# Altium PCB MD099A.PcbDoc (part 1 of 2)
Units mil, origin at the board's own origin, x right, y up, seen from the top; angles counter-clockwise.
Board outline 4255 x 2850 mil, 4 copper layers (Top Layer, Ground, Power, Bottom Layer), stack 61.6 mil thick; 151 components, 81 nets, 392 pads, 633 vias.
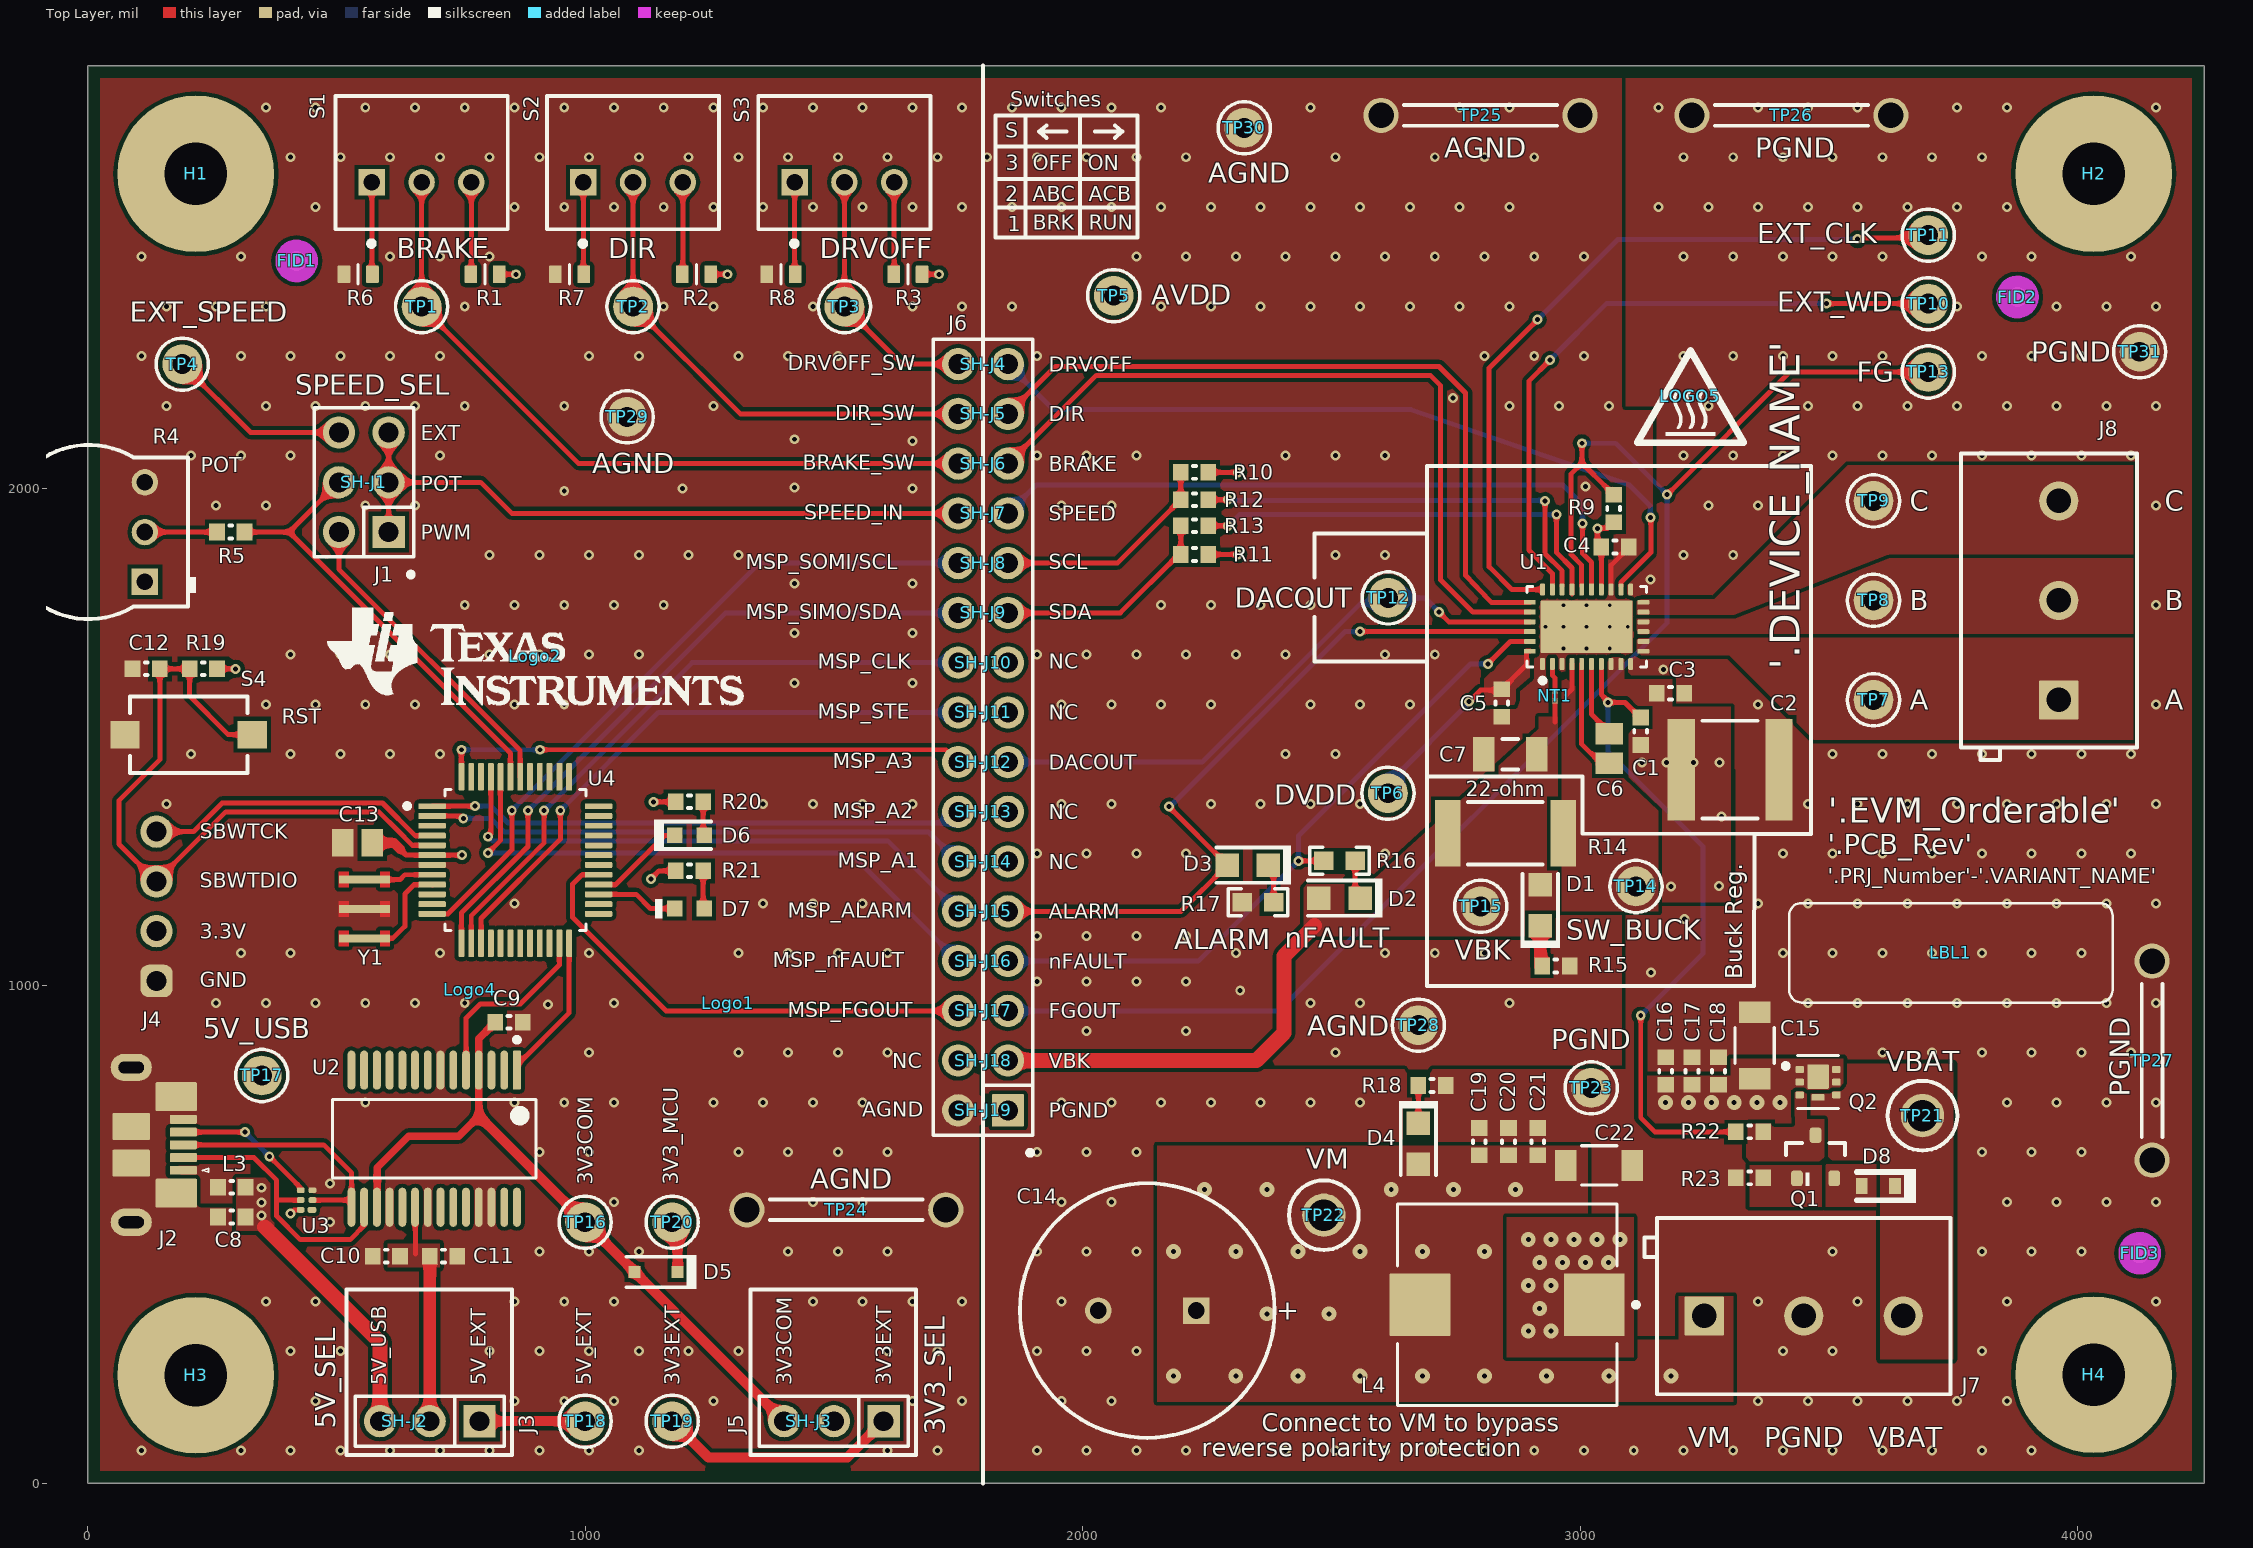
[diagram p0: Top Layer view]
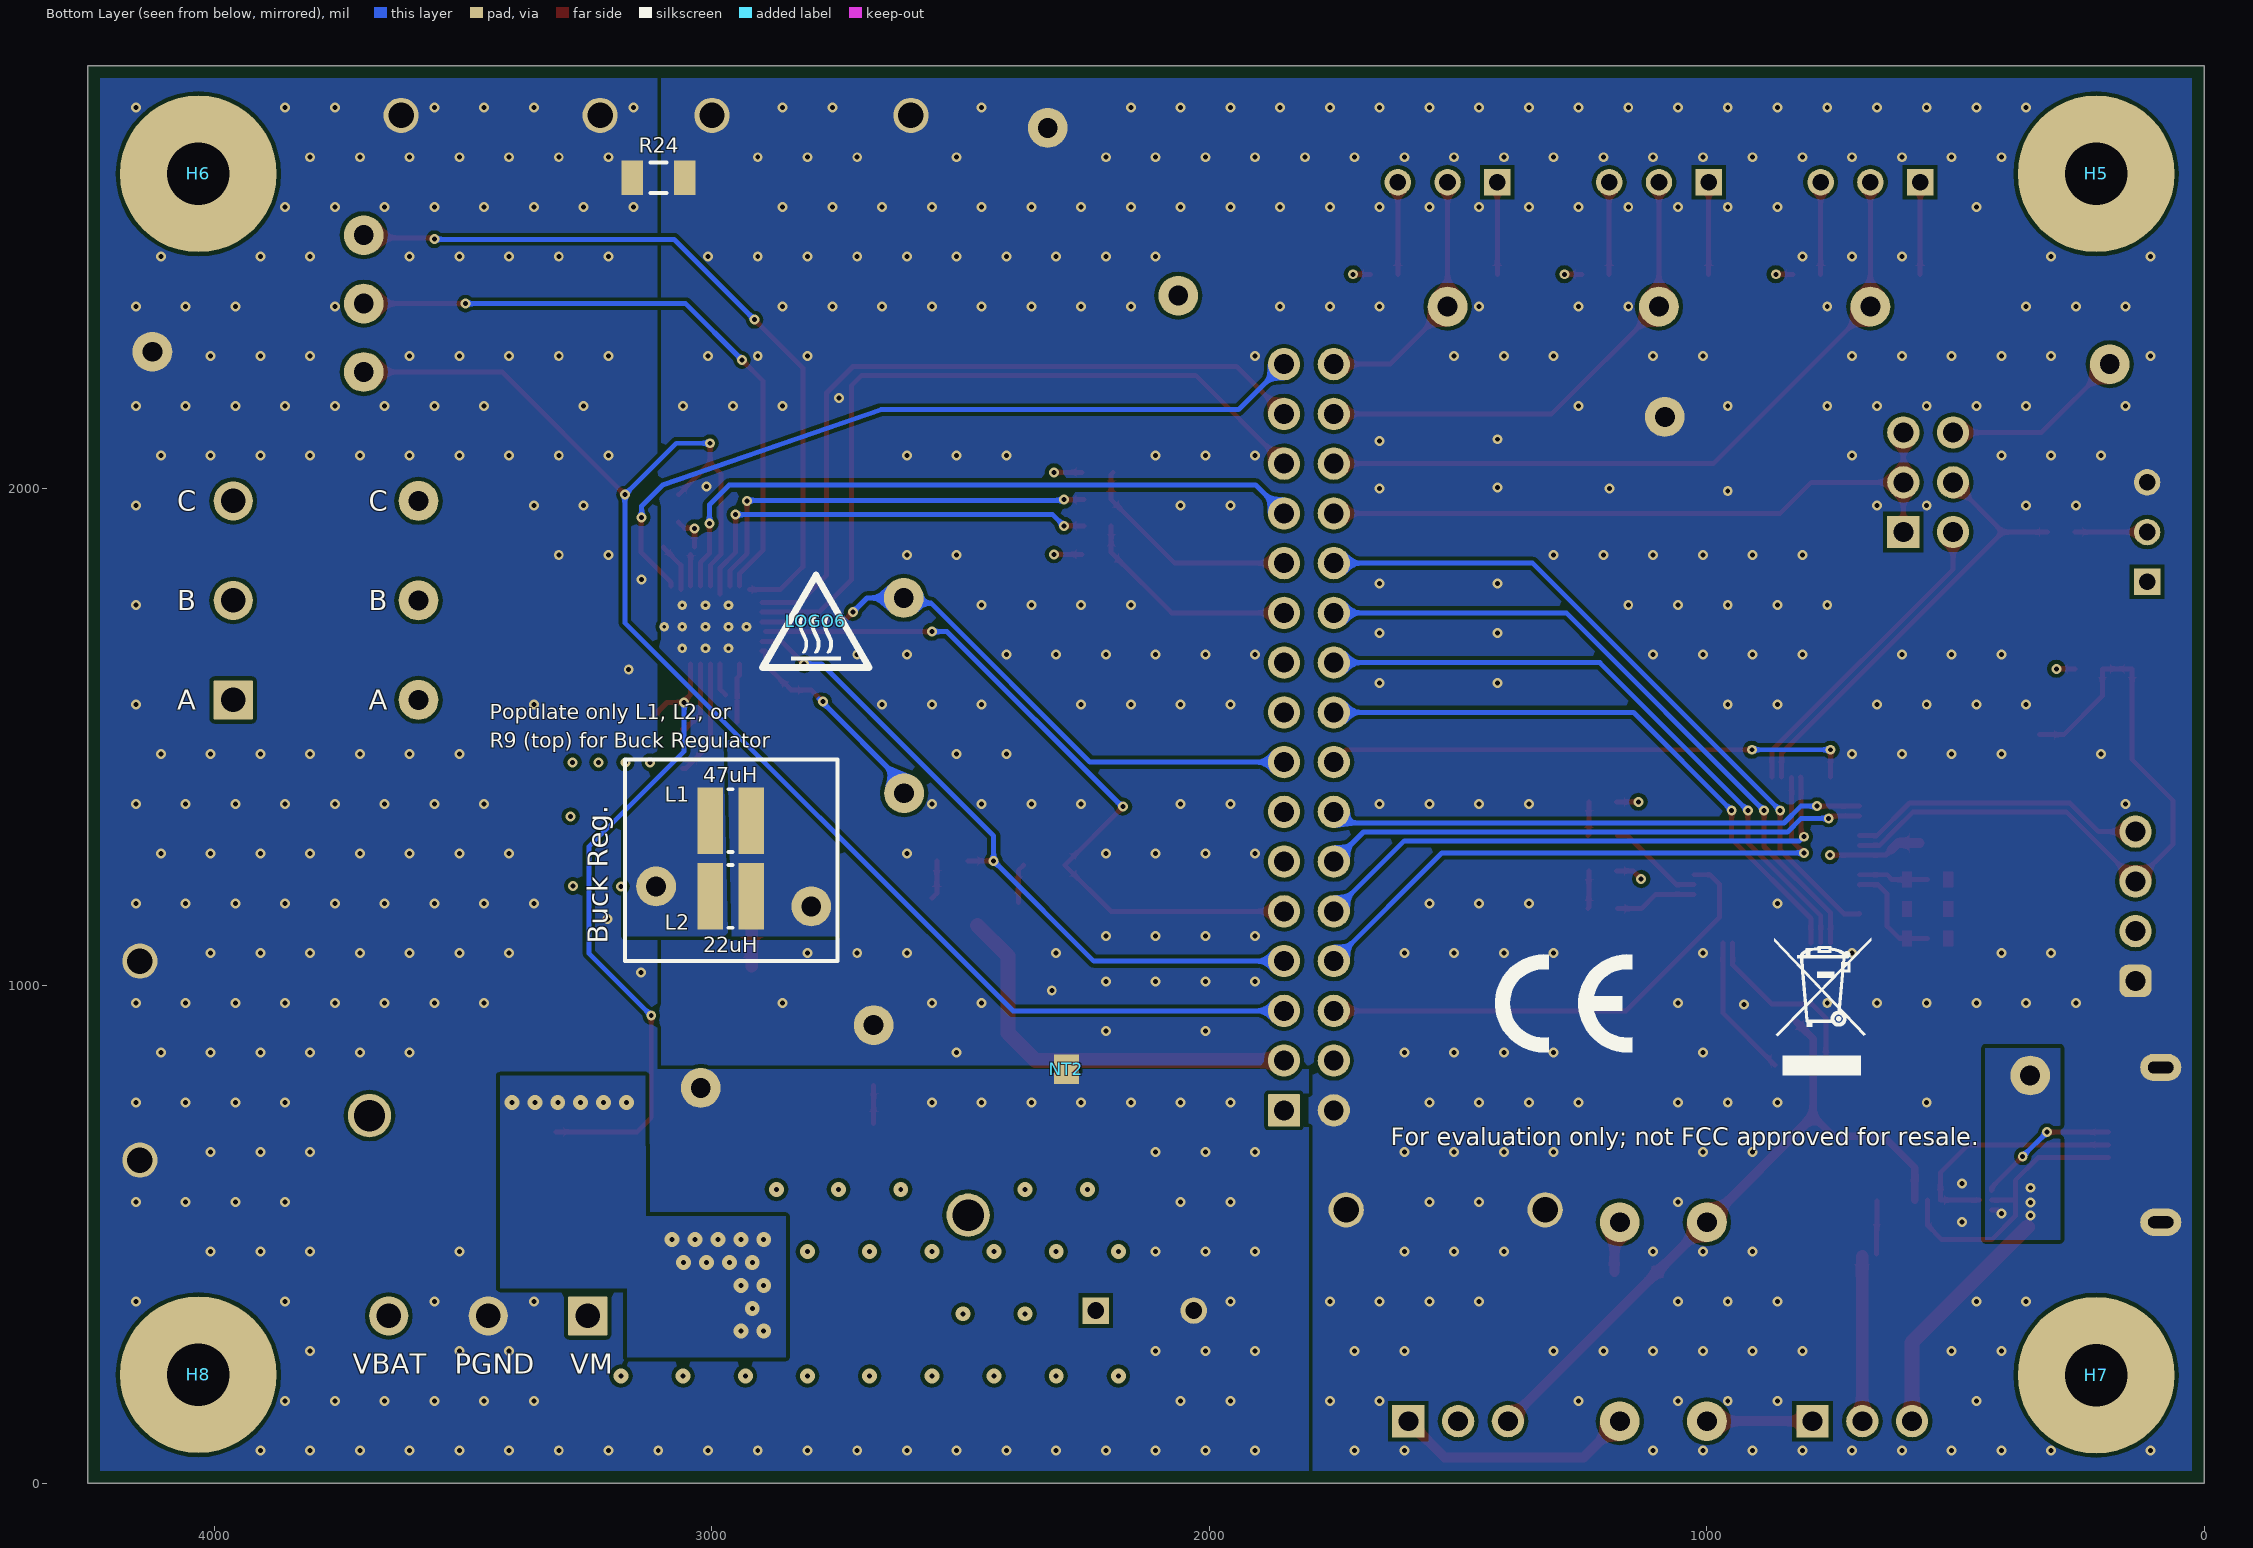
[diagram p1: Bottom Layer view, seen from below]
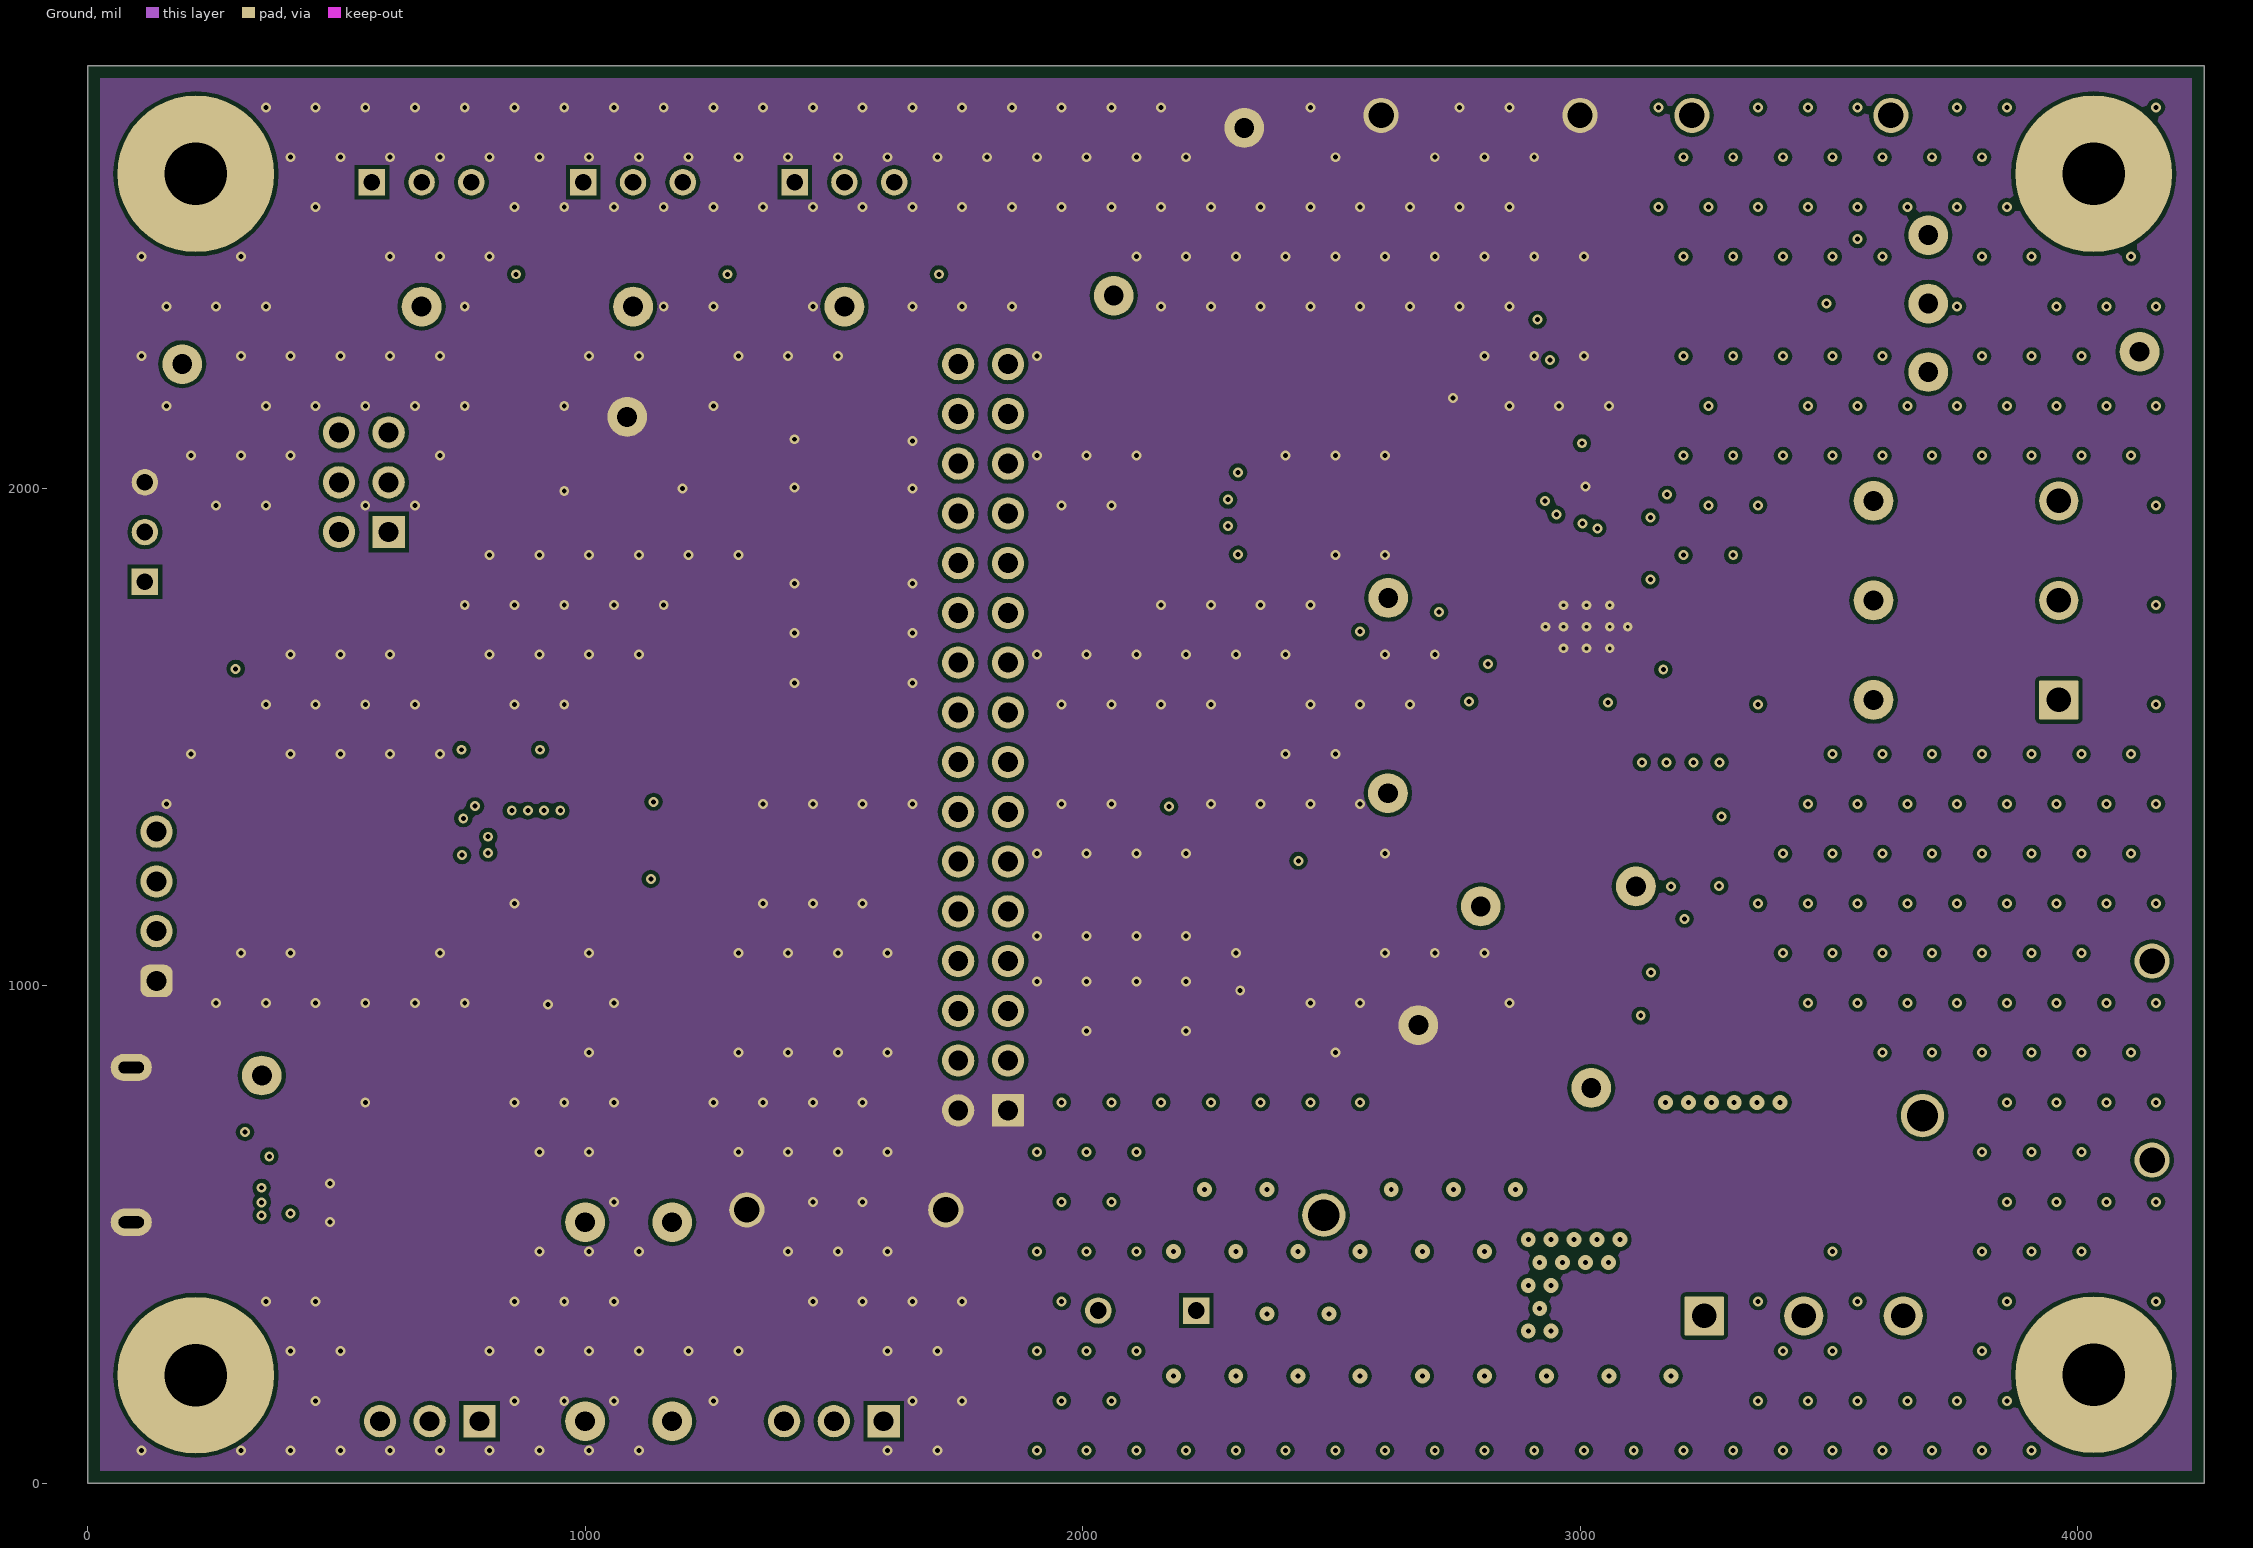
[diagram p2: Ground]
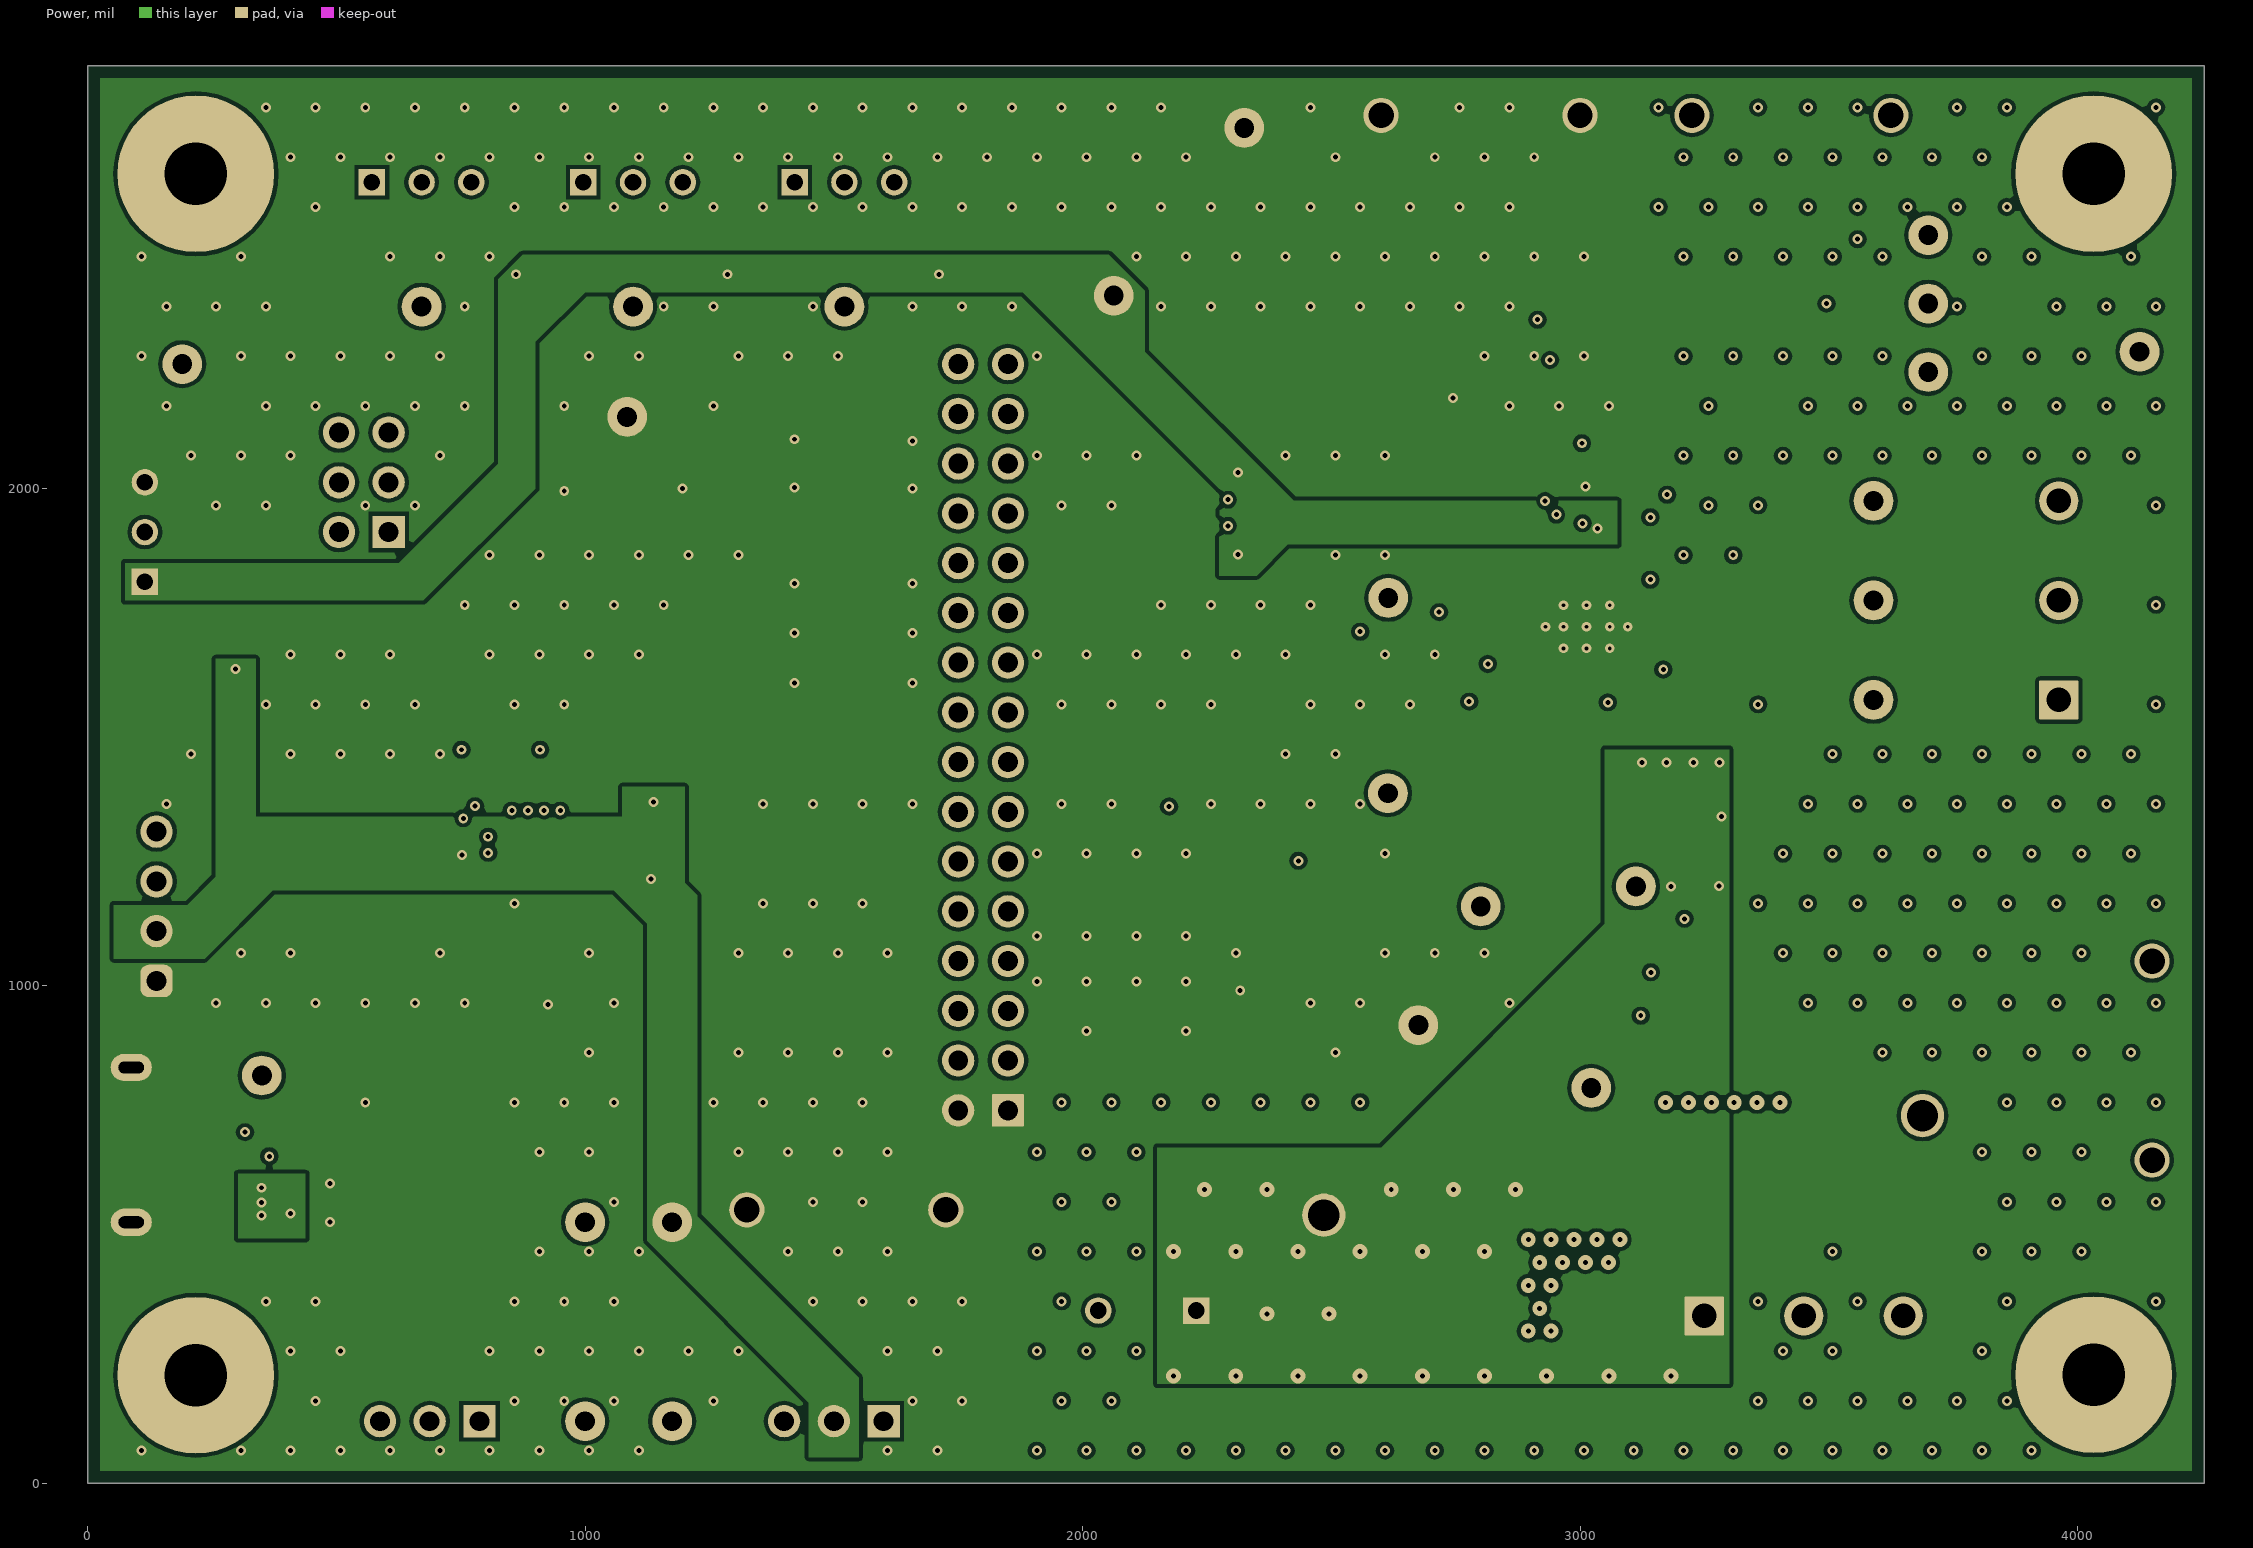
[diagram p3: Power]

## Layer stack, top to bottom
Top Solder: solder mask 0.4, Solder Resist, Dk 3.5
Top Layer: signal copper 1.4
Dielectric 1: prepreg 8, FR-4, Dk 4.2
Ground: signal copper 1.4
Dielectric 2: core 40, FR-4, Dk 4.2
Power: signal copper 1.4
Dielectric 3: prepreg 8, FR-4, Dk 4.2
Bottom Layer: signal copper 1.4
Bottom Solder: solder mask 0.4, Solder Resist, Dk 3.5

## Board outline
0,0 0,2850 4255,2850 4255,0

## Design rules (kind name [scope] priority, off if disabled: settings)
AcuteAngle [All] p1: minimum=4.50000000000000E+0001 checktracksonly=FALSE
AssemblyTestPointUsage [All] p1: valid=2
BoardOutlineClearance BoardOutlineClearance_MountingHoles [OnCopper and InComponentClass('Mounting Holes')] p1: gap=39.37 ignorepadtopadclearanceinfootprint=FALSE
BoardOutlineClearance BoardOutlineClearance_Poly [OnCopper and IsPoly] p2: gap=25 ignorepadtopadclearanceinfootprint=FALSE
BoardOutlineClearance [OnCopper and Not InComponentClass('Logo') and not InComponentClass('FiducialMark') and not InRegion(1000,500,4000,800) and not InPoly] p3: gap=30 ignorepadtopadclearanceinfootprint=FALSE
Clearance "Stitching AGND" [IsStitchingVia and InNet('AGND') vs (IsVia and (Not IsStitchingVia)) Or IsPad] p1: gap=70 ignorepadtopadclearanceinfootprint=TRUE
Clearance Clearance_Keepouts [((IsTrack Or IsArc) And Not InPoly) And IsFree and IsKeepOut vs ((IsTrack Or IsArc) And Not InPoly) And IsFree and IsKeepOut] p2: gap=0 ignorepadtopadclearanceinfootprint=FALSE
Clearance Clearance_Poly [InPolygon] p3: gap=7.87 ignorepadtopadclearanceinfootprint=TRUE
Clearance Clearance_FiducialMark [IsKeepOut and InComponentClass('FiducialMark') vs IsPad and InComponentClass('FiducialMark')] p4: gap=0 ignorepadtopadclearanceinfootprint=FALSE
Clearance [All] p5: gap=7.87 ignorepadtopadclearanceinfootprint=TRUE
ComponentClearance ComponentClearance_MountingHoles_FiducialMarks [InComponentClass('Mounting Holes') vs InComponentClass('FiducialMark')] p1: gap=50 collisioncheckmode=3 verticalgap=10 showdistances=FALSE
ComponentClearance ComponentClearance_Shunt [InComponentClass('Header') vs InComponentClass('Shunt')] p2: gap=0 collisioncheckmode=3 verticalgap=0 showdistances=FALSE
ComponentClearance ComponentClearance_Logo [InComponentClass('Logo')] p3: gap=50 collisioncheckmode=3 verticalgap=10 showdistances=FALSE
ComponentClearance ComponentClearance_ScrewToNut [(HasFootprint('NY PMS 440 0025 PH')) vs (HasFootprint('Keystone_1902C'))] p4: gap=5 collisioncheckmode=3 verticalgap=10 showdistances=FALSE
ComponentClearance ComponentClearance_MountingHoles [InComponentClass('Mounting Holes')] p5: gap=150 collisioncheckmode=3 verticalgap=100000 showdistances=FALSE
ComponentClearance ComponentClearance_SmallPassives [HasFootprint('0201*') or HasFootprint('0402*') or HasFootprint('0508') or HasFootprint('0603*') or HasFootprint('0612') or HasFootprint('0805*') or HasFootprint('0815*') or HasFootprint('0830*') or HasFootprint('1206*') or HasFootprint('1210*') or HasFootprint('1808*') or HasFootprint('1812*') or HasFootprint('1825*') or HasFootprint('2010*') or HasFootprint('2220*') or HasFootprint('2225*') or HasFootprint('2512*') or HasFootprint('2728*') or HasFootprint('3518*') vs HasFootprint('0201*') or HasFootprint('0402*') or HasFootprint('0508') or HasFootprint('0603*') or HasFootprint('0612') or HasFootprint('0805*') or HasFootprint('0815*') or HasFootprint('0830*') or HasFootprint('1206*') or HasFootprint('1210*') or HasFootprint('1808*') or HasFootprint('1812*') or HasFootprint('1825*') or HasFootprint('2010*') or HasFootprint('2220*') or HasFootprint('2225*') or HasFootprint('2512*') or HasFootprint('2728*') or HasFootprint('3518*')] p6: gap=14.96 collisioncheckmode=3 verticalgap=10 showdistances=FALSE
ComponentClearance ComponentClearance_THtoSMT [IsThruComponent vs IsSMTComponent] p7: gap=0 collisioncheckmode=3 verticalgap=0 showdistances=FALSE
ComponentClearance ComponentClearance_THtoTH [IsThruComponent vs IsThruComponent] p8: gap=0 collisioncheckmode=3 verticalgap=0 showdistances=FALSE
ComponentClearance [All] p9: gap=0 collisioncheckmode=3 verticalgap=0 showdistances=FALSE
DiffPairsRouting [All] p1: maxlimit=100 minlimit=10 mostfreqgap=10 toplayer_minwidth=15 toplayer_maxwidth=15 toplayer_prefwidth=15 midlayer1_minwidth=15 midlayer1_maxwidth=15 midlayer1_prefwidth=15 midlayer2_minwidth=15 midlayer2_maxwidth=15 midlayer2_prefwidth=15 bottomlayer_minwidth=15 bottomlayer_maxwidth=15 bottomlayer_prefwidth=15 maxuncoupledlength=1000
FabricationTestPointUsage TestPointUsage [All] p1: valid=2 allowmultiple=FALSE
FabricationTestpoint Testpoint [All] p1: side=3 testpointundercomponent=TRUE minsize=40 maxsize=100 preferedsize=60 minholesize=0 maxholesize=40 preferedholesize=32 testpointgrid=1 allowsidetop=TRUE allowsidebottom=TRUE usegrid=TRUE gridtolerance=0.01
FanoutControl Fanout_LCC [IsLCC] p1: bgadir=Out bgaviamode=Centered fanoutstyle=Auto fanoutdirection=Alternating viagrid=1 // Fanout_LCC (Default Rule)
FanoutControl Fanout_BGA [IsBGA] p2: bgadir=Out bgaviamode=Centered fanoutstyle=Auto fanoutdirection=Alternating viagrid=1 // Fanout_BGA (Default Rule)
FanoutControl Fanout_Default [All] p4: bgadir=Out bgaviamode=Centered fanoutstyle=Auto fanoutdirection=Alternating viagrid=1 // Fanout_Default (Default Rule)
FanoutControl Fanout_Small [(CompPinCount < 5)] p5: bgadir=Out bgaviamode=Centered fanoutstyle=Auto fanoutdirection=OutThenIn viagrid=1 // Fanout_Small (Default Rule)
HoleSize [All] p1: absolutevalues=TRUE maxlimit=200 minlimit=1 maxpercent=80.000 minpercent=20.000
MinimumAnnularRing MinimumAnnularRing_ThermalPadVias [IsVia and InAnyComponent] p1: minimumring=1
MinimumAnnularRing [All] p2: minimumring=1
MinimumSolderMaskSliver MinimumSolderMaskSliver_Logo [InComponentClass('Logo') vs InComponentClass('Logo')] p1: minsoldermaskwidth=0.7
MinimumSolderMaskSliver [All] p2: minsoldermaskwidth=1
PlaneConnect [All] p1: planeconnectstyle=Relief reliefexpansion=10 reliefentries=4 reliefconductorwidth=10 reliefairgap=10
PolygonConnect [All] p1: connectstyle=Direct reliefconductorwidth=10 reliefentries=4 polygonreliefangle="90 Angle" airgapwidth=10
RoutingVias ThermalPadVias [IsVia and InAnyComponent] p1: holewidth=7.87 width=19.68 viastyle="Through Hole" minholewidth=7.87 minwidth=19.68 maxholewidth=12.99 maxwidth=23.62
RoutingVias [All] p2: holewidth=10 width=25 viastyle="Through Hole" minholewidth=7 minwidth=20 maxholewidth=15 maxwidth=30
SilkToBoardRegionClearance [Not ((IsComment or IsDesignator) And (Hide <> 'False')) and not InRegion(1000,500,4000,800)] p1:
SilkToSilkClearance SilkToSilkClearance_Pb-FreeLogo [(HasFootprint('Pb-Free_Overlay_Medium') OR HasFootprint('Pb-Free_Overlay_Small')) vs (HasFootprint('Pb-Free_Overlay_Medium') OR HasFootprint('Pb-Free_Overlay_Small'))] p1: silktosilkclearance=1
SilkToSilkClearance [All] p2: silktosilkclearance=1
SilkToSolderMaskClearance [IsPad] p1: minsilkscreentomaskgap=1 clearancetoexposedcopper=TRUE
SolderMaskExpansion [All] p1: expansion=1.97 istentingtop=FALSE
UnRoutedNet [All] p1: checkbadconnections=TRUE
Width [All] p1: maxlimit=100 minlimit=6 preferedwidth=10 checkconnectedcopper=TRUE
14 further rules are at their usual default settings.

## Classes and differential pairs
component class Label: LBL1 LBL044_026
component class "Mounting Holes": H1 H2 H3 H4 H009_017 H009_041 H047_017
component class MD099_INTERFACE: C8 C9 C10 C11 C12 C012_028 C13 C014_019 C015_024 C038_030 C039_029 D5 D6 D7 D019_028 D032_027 D036_026 J2 J3 J4 J5 J6 J007_022 J008_026 J021_016 J024_030 L3 L036_028 R016_039 R19 R20 R21 R029_035 R035_028 S4 S017_041 SH-J2 SH-J3 SH-J4 SH-J5 SH-J6 SH-J7 SH-J8 SH-J9 SH-J10 SH-J11 SH-J12 SH-J13 SH-J013_016 SH-J14 SH-J15 SH-J16 SH-J17 SH-J18 SH-J19 SH-J021_016 SH-J024_022 SH-J024_023 SH-J024_024 SH-J024_031 SH-J024_032 SH-J024_034 SH-J024_035 SH-J024_036 TP013_039 TP16 TP17 TP18 TP19 TP20 TP022_020 TP038_027 TP042_031 U2 U3 U4 U011_021 U013_022 U037_032 Y1 Y012_026
component class MD099_CONTROL: J1 J008_026 R1 R2 R3 R4 R5 R6 R7 R8 R009_034 R012_039 R014_039 R029_035 R035_028 R037_034 S1 S2 S3 S008_030 S017_041 SH-J1 SH-J012_035 TP1 TP2 TP3 TP4 TP008_037 TP022_020 TP043_039
component class Shunt: SH-J1 SH-J2 SH-J3 SH-J4 SH-J5 SH-J6 SH-J7 SH-J8 SH-J9 SH-J10 SH-J11 SH-J12 SH-J012_035 SH-J13 SH-J013_016 SH-J14 SH-J15 SH-J16 SH-J17 SH-J18 SH-J19 SH-J021_016 SH-J024_022 SH-J024_023 SH-J024_024 SH-J024_031 SH-J024_032 SH-J024_034 SH-J024_035 SH-J024_036
component class MD099_POWER_AND_CONNECTORS: AGND AGND1 C012_028 C14 C014_019 C15 C16 C17 C18 C19 C20 C21 C22 C028_018 C036_022 C038_030 C039_029 D8 D042_021 J7 J8 J10 J11 J041_018 J046_033 L4 L036_027 NT2 NT029_023 PGND PGND2 PGND3 Q1 Q2 Q041_021 R22 R23 R24 R032_027 R036_025 R45 TP013_039 TP016_020 TP017_036 TP018_020 TP21 TP22 TP022_020 TP23 TP24 TP25 TP26 TP27 TP28 TP29 TP30 TP31 TP033_024 TP038_027 TP043_037 TP043_040 TP_AGND1 TP_AGND2 TP_PGND vm VM1
component class MD099_DRIVER: 1 A1 B1 C1 C2 C3 C4 C5 C6 C7 C012_028 C014_019 C015_024 C028_018 C034_022 C036_022 D1 D2 D3 D4 D018_019 D019_026 D019_028 ILIM1 L1 L2 L036_027 L036_028 NT1 NT036_031 R9 R10 R11 R12 R13 R14 R15 R16 R17 R18 R029_034 R029_035 TP5 TP6 TP7 TP8 TP9 TP10 TP11 TP12 TP13 TP013_039 TP14 TP15 TP017_036 TP018_020 TP022_020 TP034_042 TP038_027 TP042_031 TP043_039 U1 U011_021
component class Header: J1 J3 J4 J5 J6 J007_022 J008_026 J10 J021_016 J024_030
component class Logo: Logo2 Logo5
component class MD099_HARDWARE: FID1 FID2 FID3 FID011_039 FID045_039 FID048_019 H1 H2 H3 H4 H5 H6 H7 H8 H009_017 H009_041 H047_017 H047_041 LBL1 LBL044_026 Logo1 Logo2 Logo3 LOGO4 Logo5 LOGO6 Logo015_031 LOGO034_032 ZZ1 ZZ2 ZZ3 ZZ4 ZZ007_047 ZZ007_049
component class FiducialMark: FID1 FID2 FID3 FID011_039 FID045_039 FID048_019
component class AssemblyNote: ZZ1 ZZ2 ZZ3 ZZ4 ZZ007_047 ZZ007_049

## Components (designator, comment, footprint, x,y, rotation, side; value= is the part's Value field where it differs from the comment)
C1 "EMK107B7105KAHT" 0603L 3121.91,1511.99 r270 top value=1uF
C2 "22201C106MAT2A" 2220_280L 3301.65,1434.78 r0 top value=10uF
C3 "GRM188R72A104KA35D" 0603L 3182.03,1588.3 r0 top value=0.1uF
C4 "C0603C105K9RACAUTO" 0603L 3070.37,1882.5 r180 top value=1uF
C5 "GCM188R70J225KE22D" 0603L 2842.85,1568.83 r90 top value=2.2uF
C6 "CGA4J2X7R2A473K125AA" 0805L 3059.14,1477.04 r270 top value=0.047uF
C7 "GRM31CR71A226KE15L" 1206_180L 2859.96,1466 r180 top value=22uF
C8 "0603ZC104KAT2A" 0603L 289.64,535.59 r180 top value=0.1uF
C9 "0603ZC104KAT2A" 0603L 847.14,927.09 r0 top value=0.1uF
C10 "GRM188Z71A475ME15D" 0603L 600.29,456.84 r0 top value=4.7uF
C11 "0603ZC104KAT2A" 0603L 715.29,456.96 r0 top value=0.1uF
C12 "885012206034" 0603L 117.5,1637.5 r180 top value=1000pF
C13 "885012207103" 0805L 542.5,1287.5 r180 top value=1uF
C14 "ELXZ630ELL331MK20S" Chemi-Con_1250x2000 2130,347.5 r180 top value=330uF
C15 "CL31B105KCHNNNE" 1206_180 3350.96,880.34 r90 top value=1uF
C16 "CGA3E3X7S2A104K080AB" 0603L 3172.01,828.83 r90 top value=0.1uF
C17 "CGA3E2X7R2A103K080AA" 0603L 3225.22,828.83 r90 top value=0.01uF
C18 "CGA3E2X7R2A102K080AA" 0603L 3278.42,828.83 r90 top value=1000pF
C19 "CGA3E2X7R2A102K080AA" 0603L 2797.51,686.94 r90 top value=1000pF
C20 "CGA3E2X7R2A103K080AA" 0603L 2856.26,686.94 r90 top value=0.01uF
C21 "CGA3E3X7S2A104K080AB" 0603L 2915.01,686.94 r90 top value=0.1uF
C22 "CL31B105KCHNNNE" 1206_180 3038.46,639.14 r0 top value=1uF
D1 "LTST-C170KGKT" LTST-C170KGKT_Green 2920,1162.5 r270 top value=Green
D2 "LTST-C170KRKT" LED_LTST-C170_Red 2516.5,1176.5 r0 top value=Red
D3 "LTST-C170KRKT" LED_LTST-C170_Red 2332.16,1243 r0 top value=Red
D4 "LTST-C170KGKT" LTST-C170KGKT_Green 2675,682.5 r90 top value=Green
D5 "BAT165E6327HTSA1" SOD-323 1142.5,425 r180 top value=40V
D6 "LTST-C190KRKT" LED_LTST-C190_Red 1209.64,1302.7 r180 top value=Red
D7 "LTST-C190KGKT" LED_LTST-C190_G 1209.64,1155.59 r180 top value=Green
D8 "CDSU101A" SOD-523F 3599.64,597.8 r180 top value=90V
FID1 "Fiducial" Fiducial10-20 420,2457.5 r0 top locked
FID2 "Fiducial" Fiducial10-20 3879.4,2385 r0 top
FID3 "Fiducial" Fiducial10-20 4125,462.5 r0 top
H1 "NY PMS 440 0025 PH" "NY PMS 440 0025 PH" 217.5,2632.5 r0 top
H2 "NY PMS 440 0025 PH" "NY PMS 440 0025 PH" 4032.5,2632.5 r0 top
H3 "NY PMS 440 0025 PH" "NY PMS 440 0025 PH" 217.5,217.5 r0 top
H4 "NY PMS 440 0025 PH" "NY PMS 440 0025 PH" 4032.5,218.36 r0 top
H5 "Nut" Keystone_1902C 217.5,2632.5 r180 bottom
H6 "Nut" Keystone_1902C 4032.5,2632.5 r180 bottom
H7 "Nut" Keystone_1902C 217.5,217.5 r180 bottom
H8 "Nut" Keystone_1902C 4032.5,218.36 r180 bottom
J1 "Header_3x2" TSW-103-07-G-D 555.01,2012.5 r90 top
J2 "1051640001" Molex_1051640001 30.41,680.59 r270 top
J3 "Header_3x1" PBC03SAAN 687.5,125 r180 top
J4 "TSW-104-07-G-S" TSW-104-07-G-S 138.36,1160.18 r90 top
J5 "Header_3x1" PBC03SAAN 1500,125 r180 top
J6 "TSW-116-07-G-D" TSW-116-07-G-D 1800,1500 r90 top
J7 "POWER_IN" On-Shore_ED120_3DS 3449.83,336.64 r0 top
J8 "MOTOR_OUT" On-Shore_ED120_3DS 3962.5,1775 r90 top
L1 "78438335470" WE-MAIA_3015 2962.5,1332.5 r180 bottom value=47uH
L2 "78438335220" WE-MAIA_3015 2962.5,1180 r180 bottom value=22uH
L3 "BLM18SG121TZ1D" 0603L 289.64,595.24 r180 top
L4 "HCM1A1104V2-1R0-R" FP-HCM1A1104V2-1R0-R_SMD2-MFG 2853.46,359.14 r180 top value=1uH
LBL1 "THT-14-423-10" Label_650x200 3745.5,1066.57 r180 top
Logo1 "CE Mark" CE_Mark_5mm 1287.85,965 r180 top
Logo2 "Texas Instruments" TI_Stacked_Overlay_Small 900,1662.5 r0 top
Logo3 "FCC disclaimer" FCC_disclaimer 8817.5,5262.5 r90 top
Logo4 "WEEE logo" WEEE_Minimum 769.14,992.5 r180 top
LOGO5 "CAUTION HOT SURFACE" IEC_HotSurface_Small 3222.08,2185 r0 top
LOGO6 "CAUTION HOT SURFACE" IEC_HotSurface_Small 2791,1733.5 r180 bottom
NT1 "Net-Tie" Net-Tie_10mil 2949.39,1583.2 r270 top net-tie
NT2 "Net-Tie" Net-Tie_50milWide_30milLong 2287.5,832.5 r270 bottom net-tie
Q1 "FMMT620TA" SOT-23L 3473.46,656.64 r90 top value="80 V"
Q2 "BUK9D23-40EX" FP-BUK9D23-40EX_SOT1220-MFG 3478.46,806.64 r0 top
R1 "ERA-3ARB103V" FP-ERA-3ARB103V_0603-MFG 798.83,2430.7 r0 top value=10k
R2 "ERA-3ARB103V" FP-ERA-3ARB103V_0603-MFG 1223.83,2430.7 r0 top value=10k
R3 "ERA-3ARB103V" FP-ERA-3ARB103V_0603-MFG 1648.83,2430.7 r0 top value=10k
R4 "3352T-1-253LF" Bourns_3352T 115,1912.5 r90 top value="25 kohm"
R5 "ERJ-3GEY0R00V" 0603L 287.5,1912.5 r180 top value=0
R6 "ERA-3ARB103V" FP-ERA-3ARB103V_0603-MFG 543.77,2430.7 r0 top value=10k
R7 "ERA-3ARB103V" FP-ERA-3ARB103V_0603-MFG 968.71,2430.7 r0 top value=10k
R8 "ERA-3ARB103V" FP-ERA-3ARB103V_0603-MFG 1393.71,2430.7 r0 top value=10k
R9 "CRCW06035K10JNEA" 0603L 3067.5,1960 r270 top value=5.1k
R10 "CRCW06035K10JNEA" 0603L 2225,2032.5 r180 top value=5.1k
R11 "CRCW06035K10JNEA" 0603L 2225,1867.5 r180 top value=5.1k
R12 "ERJ-3GEY0R00V" 0603L 2225,1977.5 r0 top value=0
R13 "ERJ-3GEY0R00V" 0603L 2225,1925 r0 top value=0
R14 "CRCW251222R0JNEGHP" 2512 2850,1306.76 r180 top value=22
R15 "RC0603FR-071KL" 0603L 2951.5,1040 r180 top value=1.00k
R16 "RC0603FR-071KL" 0603 2516.5,1251.5 r0 top value=1.00k
R17 "RC0603JR-07470RL" 0603 2352.5,1168 r0 top value=470
R18 "RT0603BRD074K7L" 0603L 2702.56,800 r180 top value=4.70k
R19 "RC0603JR-0747KL" 0603L 232.5,1637.5 r0 top value=47k
R20 "RC0603JR-07470RL" 0603L 1209.64,1370.2 r180 top value=470
R21 "RC0603JR-07470RL" 0603L 1209.64,1231.43 r180 top value=470
R22 "CRCW060310K0JNEA" 0603L 3340.96,706.64 r0 top value=10k
R23 "CRCW060310K0JNEA" 0603L 3340.96,614.14 r180 top value=10k
R24 "RCA12060000ZSEA" 1206L 3107.5,2625 r0 bottom value=0
S1 "SW_SPDT_COM2_1_3" SW_B12AP 671.27,2655.07 r90 top
S2 "SW_SPDT_COM2_1_3" SW_B12AP 1096.27,2655.07 r90 top
S3 "SW_SPDT_COM2_1_3" SW_B12AP 1521.27,2655.07 r90 top
S4 "SW_SPST-single" SW_434121025816 203,1505.27 r180 top
SH-J1 "SNT-100-BK-G" SNT-100-BK-G 555,2012.5 r180 top value=1x2
SH-J2 "SNT-100-BK-G" SNT-100-BK-G 637.5,125 r0 top value=1x2
SH-J3 "SNT-100-BK-G" SNT-100-BK-G 1450,125 r0 top value=1x2
SH-J4 "SNT-100-BK-G" SNT-100-BK-G 1800,2250 r180 top value=1x2
SH-J5 "SNT-100-BK-G" SNT-100-BK-G 1800,2150 r180 top value=1x2
SH-J6 "SNT-100-BK-G" SNT-100-BK-G 1800,2050 r180 top value=1x2
SH-J7 "SNT-100-BK-G" SNT-100-BK-G 1800,1950 r180 top value=1x2
SH-J8 "SNT-100-BK-G" SNT-100-BK-G 1800,1850 r180 top value=1x2
SH-J9 "SNT-100-BK-G" SNT-100-BK-G 1800,1750 r180 top value=1x2
SH-J10 "SNT-100-BK-G" SNT-100-BK-G 1800,1650 r180 top value=1x2
SH-J11 "SNT-100-BK-G" SNT-100-BK-G 1800,1550 r180 top value=1x2
SH-J12 "SNT-100-BK-G" SNT-100-BK-G 1800,1450 r180 top value=1x2
SH-J13 "SNT-100-BK-G" SNT-100-BK-G 1800,1350 r180 top value=1x2
SH-J14 "SNT-100-BK-G" SNT-100-BK-G 1800,1250 r180 top value=1x2
SH-J15 "SNT-100-BK-G" SNT-100-BK-G 1800,1150 r180 top value=1x2
SH-J16 "SNT-100-BK-G" SNT-100-BK-G 1800,1050 r180 top value=1x2
SH-J17 "SNT-100-BK-G" SNT-100-BK-G 1800,950 r0 top value=1x2
SH-J18 "SNT-100-BK-G" SNT-100-BK-G 1800,850 r0 top value=1x2
SH-J19 "SNT-100-BK-G" SNT-100-BK-G 1800,750 r0 top value=1x2
TP1 "BRAKE_SW" Keystone5002 671.27,2365.7 r270 top
TP2 "DIR_SW" Keystone5002 1096.27,2365.7 r270 top
TP3 "DRVOFF_SW" Keystone5002 1521.27,2365.7 r270 top
TP4 "EXT_SPEED" Keystone5002 190,2250 r90 top
TP5 "AVDD" Keystone5000 2062.62,2387.68 r90 top
TP6 "DVDD" Keystone5000 2613.86,1387.5 r90 top
TP7 "OUTA" Keystone5000 3590,1575 r90 top
TP8 "OUTB" Keystone5000 3590,1775 r90 top
TP9 "OUTC" Keystone5000 3590,1975 r90 top
TP10 "EXT_WD" Keystone5002 3700,2371.75 r90 top
TP11 "EXT_CLK" Keystone5002 3700,2509.25 r90 top
TP12 "DACOUT" Keystone5002 2614.5,1780 r90 top
TP13 "FG" Keystone5002 3700,2234.25 r90 top
TP14 "SW_BUCK" Keystone5000 3112.5,1200 r90 top
TP15 "VBK" Keystone5000 2800.35,1159.97 r90 top
TP16 "3V3COM" Keystone5000 1000,525 r90 top
TP17 "5V_USB" Keystone5000 350,820 r90 top
TP18 "5V_EXT" Keystone5000 1000,125 r90 top
TP19 "3V3EXT" Keystone5000 1175,125 r90 top
TP20 "3V3_MCU" Keystone5000 1175,525 r90 top
TP21 "VBAT" Keystone5005 3688.46,739.3 r180 top
TP22 "VM" Keystone5005 2485,539.22 r180 top
TP23 "PGND" Keystone5001 3022.5,795 r270 top
TP24 "AGND" Harwin_D3082-05 1525,550 r180 top
TP25 "AGND" Harwin_D3082-05 2800,2750 r180 top
TP26 "PGND" Harwin_D3082-05 3425,2750 r180 top
TP27 "PGND" Harwin_D3082-05 4150,850 r90 top
TP28 "AGND" Keystone5001 2675,921.22 r90 top
TP29 "AGND" Keystone5001 1084.5,2144 r90 top
TP30 "AGND" Keystone5001 2325,2725 r90 top
TP31 "PGND" Keystone5001 4125,2275 r90 top
U1 "MCF8315C1VRRYR" RRY0032A-MFG 3013.29,1722.11 r90 top
U2 "FT232RNL-REEL" FP-FT232RNL-REEL_SSOP28-MFG 696.5,693 r270 top
U3 "TPD4E004DRYR" DRY0006A 440,569.59 r180 top
U4 "MSP430FR2355TPTR" PT0048A-MFG 859.64,1253.09 r0 top
Y1 "CSTCR4M00G55B-R0" Murata_CSTCR_G 556.22,1154.67 r270 top
ZZ1 "This Assembly Note is for PCB labels only" AssemblyNoteLabel 80,3455.5 r0 top
ZZ2 "These assemblies are ESD sensitive, ESD precautions shall be observed." AssemblyNote 80,3351.61 r0 top
ZZ3 "These assemblies must be clean and free from flux and all contaminants. Use of no clean flux is not acceptable." AssemblyNote 80,3263.06 r0 top
ZZ4 "These assemblies must comply with workmanship standards IPC-A-610 Class 2, unless otherwise specified." AssemblyNote 80,3174.5 r0 top

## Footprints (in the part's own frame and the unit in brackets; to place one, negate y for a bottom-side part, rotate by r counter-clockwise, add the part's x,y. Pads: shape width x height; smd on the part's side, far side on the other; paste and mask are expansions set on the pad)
0603 [mm] "0603 from SM-752 data"
  rect 1x0.95 smd: 1(-0.8,0) 2(0.8,0)
  silkscreen extent -1.52,-0.69 1.52,0.69, body extent -0.87,-0.47 0.87,0.47, height 1
0603L [mm] "0603 from SM-752 data"
  rect 0.8x0.85 smd: 1(-0.7,0) 2(0.7,0)
  silkscreen extent -0.07,-0.33 0.07,0.33, body extent -0.87,-0.47 0.87,0.47, height 1
0805L [mm] "0805 from SM-752 data"
  rect 1.1x1.4 smd: 1(-0.75,0) 2(0.75,0)
  body extent -1.1,-0.72 1.1,0.72, height 1.45
1206_180 [mm] "1206_180"
  rect 1.1x1.6 smd: 1(-1.7,0) 2(1.7,0)
  silkscreen extent -0.9,-1 0.9,1, body extent -1.75,-0.95 1.75,0.95, height 1.8
1206_180L [mm] "1206_180"
  rect 1.1x1.75 smd: 1(-1.35,0) 2(1.35,0)
  silkscreen extent -0.4,-0.77 0.4,0.77, body extent -1.75,-0.95 1.75,0.95, height 1.8
1206L [mm] "1206 from SM-752 data"
  rect 1.1x1.75 smd: 1(-1.35,0) 2(1.35,0)
  silkscreen extent -0.4,-0.77 0.4,0.77, body extent -1.7,-0.9 1.7,0.9, height 1.35
2220_280L [mm] "Chip Capacitor, Body 5.7x5.0mm, IPC High Density"
  rect 1.4x5.2 smd: 1(-2.5,0) 2(2.5,0)
  silkscreen extent -1.4,-2.5 1.4,2.5, body extent -2.95,-2.6 2.95,2.65, height 2.8
2512 [mm] "Chip Resistor, Body 6.3x3.2mm, IPC Medium Density"
  rect 1.3x3.4 smd: 1(-2.95,0) 2(2.95,0)
  silkscreen extent -1.9,-1.6 1.9,1.6, body extent -3.22,-1.67 3.22,1.67, height 0.71
AssemblyNote [mil] "Assembly Note"
AssemblyNoteLabel [mil] "Assembly Note for PCB Labels"
Bourns_3352T [mm] "TH, 3-Leads, Body 9.53x8.89mm, Pitch 2.54mm"
  rect 1.35x1.35 hole 0.85: 1(-2.54,0)
  round 1.35 hole 0.85: 2(0,0) 3(2.54,0)
  silkscreen extent -4.44,-2.6 4.44,7.31, body extent -4.44,-2.21 4.45,7.32, height 3.81
CE_Mark_5mm [mil] "Minimum text height for CE Mark"
Chemi-Con_1250x2000 [mm] "TH, 2-Leads, Dia 12.5mm, Lead Sapcing 5mm"
  rect 1.35x1.35 hole 0.85: 1(-2.5,0)
  round 1.35 hole 0.85: 2(2.5,0)
  silkscreen extent -6.5,-6.5 6.5,6.5, body extent -6.5,-6.5 6.51,6.5, height 21.5
DRY0006A [mm] "USON-6"
  rrect67% 0.45x0.3 smd paste-0.05 mask-0.05: 1(-0.275,0.5)
  rrect67% 0.4x0.3 smd paste-0.05 mask-0.05: 2(-0.3,0) 3(-0.3,-0.5) 4(0.3,-0.5) 5(0.3,0) 6(0.3,0.5)
  body extent -0.5,-0.72 0.5,0.73, height 0.58
FCC_disclaimer [mil]
Fiducial10-20 [mm]
  round 1 smd mask+0.5: 1(0,0)
  Top Layer keep-out circle w1.178: c0,0 r0.5
FP-BUK9D23-40EX_SOT1220-MFG [mm]
  rrect29% 0.43x0.35 smd paste-1000 mask+0: 1(-0.935,0.65) 2(-0.935,0) 3(-0.935,-0.65) 4(0.935,-0.65) 5(0.935,0) 6(0.935,0.65)
  rrect9% 1.1x1.25 smd paste-1000 mask+0: 7(0,0.285)
  rrect29% 0.66x0.35 smd paste-1000 mask+0: 8(0,-0.775)
  silkscreen extent -1.77,-1.35 1.05,1.35, body extent -1.25,-1.15 1.25,1.15, height 0.25
FP-ERA-3ARB103V_0603-MFG [mm] "0603 from SM-752 data"
  rrect15% 0.65x0.9 smd paste+0 mask+0: 1(-0.725,0) 2(0.725,0)
  silkscreen extent 0,-0.5 0,0.5, body extent -1.15,-0.6 1.15,0.6, height 0.25
FP-FT232RNL-REEL_SSOP28-MFG [mm]
  rrect25% 2x0.4 smd paste+0 mask+0: 1(-3.5,4.225)
  rrect100% 2x0.4 smd paste+0 mask+0: 2(-3.5,3.575) 3(-3.5,2.925) 4(-3.5,2.275) 5(-3.5,1.625) 6(-3.5,0.975) 7(-3.5,0.325) 8(-3.5,-0.325) 9(-3.5,-0.975) 10(-3.5,-1.625) 11(-3.5,-2.275) 12(-3.5,-2.925) 13(-3.5,-3.575) 14(-3.5,-4.225) 15(3.5,-4.225) 16(3.5,-3.575) 17(3.5,-2.925) 18(3.5,-2.275) 19(3.5,-1.625) 20(3.5,-0.975) 21(3.5,-0.325) 22(3.5,0.325) 23(3.5,0.975) 24(3.5,1.625) 25(3.5,2.275) 26(3.5,2.925) 27(3.5,3.575) 28(3.5,4.225)
  silkscreen extent -5.17,-5.2 2,5.2, body extent -4.6,-5.3 4.6,5.3, height 0.25
FP-HCM1A1104V2-1R0-R_SMD2-MFG [mm] "SMD, 2-Leads, Body 10.8x10mm"
  rrect3% 3.1x3.2 smd paste+0 mask+0: 1(-4.45,0) 2(4.45,0)
  silkscreen extent -6.7,-5.15 5.6,5.15, body extent -6.1,-5.25 6.1,5.25, height 0.25
Harwin_D3082-05 [mm] "Shorting Plug, 10.16mm spacing, TH"
  round 1.8 hole 1.3: 1(-5.08,0) 2(5.08,0)
  silkscreen extent -3.9,-0.53 3.9,0.53, body extent -5.6,-0.52 5.61,0.52, height 6.63
IEC_HotSurface_Small [mil]
  silkscreen extent -107,-93 107,92
Keystone5000 [mil] "For Keystone 500x miniature loop terminals"
  round 80 hole 40: 1(0,0)
  silkscreen extent -52,-52 52,52, body extent -49,-49 49,49, height 182
Keystone5001 [mil] "For Keystone 500x miniature loop terminals"
  round 80 hole 40: 1(0,0)
  silkscreen extent -52,-52 52,52, body extent -49,-49 49,49, height 182
Keystone5002 [mil] "For Keystone 500x miniature loop terminals"
  round 80 hole 40: 1(0,0)
  silkscreen extent -52,-52 52,52, body extent -49,-49 49,49, height 182
Keystone5005 [mil] "Keystone Compact loops"
  round 87 hole 63: 1(0,0)
  silkscreen extent -70,-70 70,70, body extent -63,-63 62,63, height 225
Keystone_1902C [mil] "Hex Standoff, 4-40 threaded, nylon"
  round 1 on Mech4: 0(0,0)
  body extent -145,-126 146,126, height 501
Label_650x200 [mil] "Thermal Transfer Label"
  round 1 on Mech13: 0(0,0)
  silkscreen extent -325,-100 325,100, body extent -325,-100 325,100, height 1
LED_LTST-C170_Red [mm] "LITE-ON"
  rect 1.2x1.2 smd: 1(-1.05,0) 2(1.05,0)
  silkscreen extent -1.6,-1 2.2,1, body extent -1.05,-0.67 1.05,0.67, height 1.1
LED_LTST-C190_G [mm] "Lite-On"
  rect 0.8x0.8 smd: 1(-0.75,0) 2(0.75,0)
  silkscreen extent 1.37,-0.5 1.75,0.5, body extent -0.85,-0.45 0.85,0.45, height 0.9
LED_LTST-C190_Red [mm] "Lite-On"
  rect 0.8x0.8 smd: 1(-0.75,0) 2(0.75,0)
  silkscreen extent -1.1,-0.8 1.8,0.8, body extent -0.85,-0.45 0.85,0.45, height 0.9
LTST-C170KGKT_Green [mm] "LITE-ON"
  rect 1.2x1.2 smd: 1(-1.05,0) 2(1.05,0)
  silkscreen extent -1.6,-1 2.2,1, body extent -1.05,-0.67 1.05,0.67, height 1.1
Molex_1051640001 [mm] "Receptacle, USB 2.0, Micro B, 5 Pos, 0.65mm Pitch, R/A, SMT"
  rrect22% 0.45x1.38 smd: 1(1.3,4.11) 2(0.65,4.11) 3(0,4.11) 4(-0.65,4.11) 5(-1.3,4.11)
  rrect7% 1.475x2.1 smd: 6(-2.462,3.75) 11(2.462,3.75)
  rrect100% 1.4x2.1 hole 0.6 slot 1.3 at 90 deg: 7(-3.95,1.45) 10(3.95,1.45)
  rrect7% 1.375x1.9 smd: 8(-0.937,1.45) 9(0.937,1.45)
  silkscreen extent 1.2,5.1 1.4,5.4, body extent -4.1,-0.7 4.1,4.47, height 2.45
Murata_CSTCR_G [mm] "Murata"
  rect 0.4x2.6 smd: 1(-1.5,0) 2(0,0) 3(1.5,0)
  Top Layer region: 1.1,-1.301 1.1,-0.801 1.9,-0.801 1.9,-1.301
  Top Layer region: 1.1,0.8 1.9,0.8 1.9,1.3 1.1,1.3
  Top Layer region: -1.9,-1.301 -1.9,-0.801 -1.1,-0.801 -1.1,-1.301
  Top Layer region: -1.9,0.8 -1.1,0.8 -1.1,1.3 -1.9,1.3
  Top Layer region: -0.4,-1.301 -0.4,-0.801 0.4,-0.801 0.4,-1.301
  Top Layer region: -0.4,0.8 0.4,0.8 0.4,1.3 -0.4,1.3
  body extent -2.25,-1 2.25,1, height 1.16
Net-Tie_10mil [mil] "10mil net tie, no solder mask opening, no solder paste"
  rect 10x10 smd paste-5 mask-5: 1(-10,0) 2(10,0)
  Top Layer region: -6,5 6,5 6,-5 -6,-5
Net-Tie_50milWide_30milLong [mil] "50mil net tie, no solder mask opening, no solder paste"
  rect 30x50 smd paste-20 mask-20: 1(-15,0) 2(15,0)
"NY PMS 440 0025 PH" [mm] "4-40 nylon screw and mounting hole"
  round 8 hole 3.2: 1(0,0)
  body extent -3.3,-3.3 3.3,3.3, height 2.69
On-Shore_ED120_3DS [mm] "ONSHORE"
  rrect5% 2x2 hole 1.25: 1(-5.08,0)
  round 2 hole 1.25: 2(0,0) 3(5.08,0)
  silkscreen extent -8.14,-4 7.5,5, body extent -8.32,-4 7.62,5, height 13
PBC03SAAN [mm] "Sullins 100mil, 1x3, 230 mil above insulator"
  rect 1.65x1.65 hole 1.016: 1(-2.54,0)
  round 1.65 hole 1.016: 2(0,0) 3(2.54,0)
  silkscreen extent -3.81,-1.27 3.81,1.27, body extent -3.81,-1.27 3.81,1.27, height 8.38
PT0048A-MFG [mm] "Thin QFP, 48-Leads, Body 7x7mm, Pitch 0.5mm, IPC Medium Density"
  rrect33% 1.4x0.3 smd paste-1000 mask+0: 1(-4.25,2.75) 2(-4.25,2.25) 3(-4.25,1.75) 4(-4.25,1.25) 5(-4.25,0.75) 6(-4.25,0.25) 7(-4.25,-0.25) 8(-4.25,-0.75) 9(-4.25,-1.25) 10(-4.25,-1.75) 11(-4.25,-2.25) 12(-4.25,-2.75) 25(4.25,-2.75) 26(4.25,-2.25) 27(4.25,-1.75) 28(4.25,-1.25) 29(4.25,-0.75) 30(4.25,-0.25) 31(4.25,0.25) 32(4.25,0.75) 33(4.25,1.25) 34(4.25,1.75) 35(4.25,2.25) 36(4.25,2.75)
  rrect33% 0.3x1.4 smd paste-1000 mask+0: 13(-2.75,-4.25) 14(-2.25,-4.25) 15(-1.75,-4.25) 16(-1.25,-4.25) 17(-0.75,-4.25) 18(-0.25,-4.25) 19(0.25,-4.25) 20(0.75,-4.25) 21(1.25,-4.25) 22(1.75,-4.25) 23(2.25,-4.25) 24(2.75,-4.25) 37(2.75,4.25) 38(2.25,4.25) 39(1.75,4.25) 40(1.25,4.25) 41(0.75,4.25) 42(0.25,4.25) 43(-0.25,4.25) 44(-0.75,4.25) 45(-1.25,4.25) 46(-1.75,4.25) 47(-2.25,4.25) 48(-2.75,4.25)
  silkscreen extent -5.65,-3.6 3.6,3.6, body extent -5.05,-5.05 5.05,5.05, height 0.25
RRY0032A-MFG [mm]
  rrect40% 0.6x0.25 smd paste+0 mask+0: 1(-1.9,2.25) 2(-1.9,1.75) 3(-1.9,1.25) 4(-1.9,0.75) 5(-1.9,0.25) 6(-1.9,-0.25) 7(-1.9,-0.75) 8(-1.9,-1.25) 9(-1.9,-1.75) 10(-1.9,-2.25) 17(1.9,-2.25) 18(1.9,-1.75) 19(1.9,-1.25) 20(1.9,-0.75) 21(1.9,-0.25) 22(1.9,0.25) 23(1.9,0.75) 24(1.9,1.25) 25(1.9,1.75) 26(1.9,2.25)
  rrect40% 0.25x0.6 smd paste+0 mask+0: 11(-1.25,-2.9) 12(-0.75,-2.9) 13(-0.25,-2.9) 14(0.25,-2.9) 15(0.75,-2.9) 16(1.25,-2.9) 27(1.25,2.9) 28(0.75,2.9) 29(0.25,2.9) 30(-0.25,2.9) 31(-0.75,2.9) 32(-1.25,2.9)
  rrect4% 2.7x4.7 smd paste-1000 mask+0: 33(0,0)
  silkscreen extent -2.87,-3.05 2.05,3.05, body extent -2.3,-3.3 2.3,3.3, height 0.25
SNT-100-BK-G [mil] "Samtec STEP model"
  round 1 on Mech3: 0(0,0)
  body extent -100,-50 100,50, height 344
SOD-323 [mm] "NXP recommended land pattern"
  rect 0.6x0.6 smd paste-0.05: 1(-1.1,0) 2(1.1,0)
  silkscreen extent -2.06,-0.86 1.53,0.86, body extent -1.3,-0.67 1.3,0.68, height 1.1
SOD-523F [mm] "COMCHIP"
  rect 0.6x0.8 smd paste-0.05: 1(-0.85,0) 2(0.85,0)
  silkscreen extent -1.92,-0.87 1.1,0.87, body extent -0.9,-0.5 0.9,0.5, height 0.85
SOT-23L [mm] "SOT23, 3-Leads, Body 2.9x1.3mm, Pitch 0.95mm, Lead Span 2.5mm, IPC High Density"
  rrect50% 0.8x0.6 smd: 1(-1.1,0.95) 2(-1.1,-0.95) 3(1.1,0)
  silkscreen extent -1.5,-1.5 0.7,1.5, body extent -1.16,-1.45 1.21,1.45, height 1
SW_434121025816 [mm] "SMD, 2-Leads, Body 6x3.9mm, Pitch 6.5mm"
  rect 1.5x1.4 smd: 1(-3.25,0) 2(3.25,0)
  silkscreen extent -3,-1.95 3,1.95, body extent -3.65,-1.95 3.65,1.95, height 2.5
SW_B12AP [mm] "NKK Switches"
  rect 1.35x1.35 hole 0.85 paste-2539.97: 1(-1,2.54)
  round 1.35 hole 0.85 paste-2539.97: 2(-1,0) 3(-1,-2.54)
  silkscreen extent -4.27,-4.4 3.4,4.4, body extent -3.4,-4.39 3.4,4.39, height 22.87
TI_Stacked_Overlay_Small [mil]
  silkscreen extent -418,-98 418,98
TSW-103-07-G-D [mm] "Samtec 100mil, 2x3, 230 mil above insulator"
  rect 1.65x1.65 hole 1.016: 1(-2.54,-1.27)
  round 1.65 hole 1.016: 2(-2.54,1.27) 3(0,-1.27) 4(0,1.27) 5(2.54,-1.27) 6(2.54,1.27)
  silkscreen extent -4.83,-2.54 3.81,2.54, body extent -3.81,-2.54 3.81,2.54, height 8.38
TSW-104-07-G-S [mm] "Samtec 100mil, 1x4, 230 mil above insulator"
  rrect50% 1.65x1.65 hole 1.016: 1(-3.81,0)
  round 1.65 hole 1.016: 2(-1.27,0) 3(1.27,0) 4(3.81,0)
  body extent -5.08,-1.27 5.08,1.27, height 8.38
TSW-116-07-G-D [mm] "Samtec 100mil, 2x16, 230 mil above insulator"
  rrect6% 1.65x1.65 hole 1.016: 1(-19.05,-1.27)
  round 1.65 hole 1.016: 2(-19.05,1.27) 3(-16.51,-1.27) 4(-16.51,1.27) 5(-13.97,-1.27) 6(-13.97,1.27) 7(-11.43,-1.27) 8(-11.43,1.27) 9(-8.89,-1.27) 10(-8.89,1.27) 11(-6.35,-1.27) 12(-6.35,1.27) 13(-3.81,-1.27) 14(-3.81,1.27) 15(-1.27,-1.27) 16(-1.27,1.27) 17(1.27,-1.27) 18(1.27,1.27) 19(3.81,-1.27) 20(3.81,1.27) 21(6.35,-1.27) 22(6.35,1.27) 23(8.89,-1.27) 24(8.89,1.27) 25(11.43,-1.27) 26(11.43,1.27) 27(13.97,-1.27) 28(13.97,1.27) 29(16.51,-1.27) 30(16.51,1.27) 31(19.05,-1.27) 32(19.05,1.27)
  silkscreen extent -21.34,-2.54 20.32,2.54, body extent -20.32,-2.54 20.32,2.54, height 8.38
WE-MAIA_3015 [mm] "SMD, 2-Leads, Body 3x3mm"
  rect 1.3x3.4 smd: 1(-1.05,0) 2(1.05,0)
  silkscreen extent -0.1,-1.6 0.1,1.6, body extent -1.6,-1.6 1.6,1.6, height 1.5
WEEE_Minimum [mil] "WEEElie bin"

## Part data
C1: library part CMP-0080104-1, "CAP, CERM, 1 µF, 16 V,+/- 10%, X7R, AEC-Q200 Grade 1, 0603", Cap_Case=0603, Manufacturer="Taiyo Yuden", Supplier Part Number 1=587-3305-1-ND, TempCo=X7R, Tolerance_%=10%, Value2=16V, ValueDisplayed=1µF
C2: library part CMP-0009304-2, "CAP, CERM, 10 uF, 100 V, +/- 20%, X7R, 2220", Cap_Case=2220, Manufacturer=AVX, Supplier Part Number 1=478-9622-1-ND, TempCo=X7R, Tolerance_%=20%, Value1=Unknown, Value2=100V, ValueDisplayed=10uF
C3: library part CMP-0007469-4, "CAP, CERM, 0.1 uF, 100 V, +/- 10%, X7R, 0603", Cap_Case=0603, Manufacturer=MuRata, Supplier Part Number 1=490-3285-1-ND, TempCo=X7R, Tolerance_%=10%, Value1=Unknown, Value2=100V, ValueDisplayed=0.1uF
C4: library part CMP-0086190-1, "CAP, CERM, 1 µF, 6.3 V,+/- 10%, X7R, AEC-Q200 Grade 1, 0603", Cap_Case=0603, Manufacturer=Kemet, TempCo=X7R, Tolerance_%=10%, Value2=6.3V, ValueDisplayed=1µF
C5: library part CMP-0007134-5, "CAP, CERM, 2.2 uF, 6.3 V, +/- 10%, X7R, AEC-Q200 Grade 1, 0603", Cap_Case=0603, Manufacturer=MuRata, Supplier Part Number 1=490-5316-1-ND, TempCo=X7R, Tolerance_%=10%, Value1=Unknown, Value2=6.3V, ValueDisplayed=2.2uF
C6: library part CMP-0007970-2, "CAP, CERM, 0.047 uF, 100 V, +/- 10%, X7R, AEC-Q200 Grade 1, 0805", Cap_Case=0805, Manufacturer=TDK, Supplier Part Number 1=445-5825-1-ND, TempCo=X7R, Tolerance_%=10%, Value1="0.049089 ohm", Value2=100V, ValueDisplayed=0.047uF
C7: library part CMP-0008959-2, "CAP, CERM, 22 uF, 10 V, +/- 10%, X7R, 1206", Cap_Case=1206, Manufacturer=MuRata, Supplier Part Number 1=490-5309-1-ND, TempCo=X7R, Tolerance_%=10%, Value1=Unknown, Value2=10V, ValueDisplayed=22uF
C8 C9 C11: library part CMP-0006815-4, "CAP, CERM, 0.1 uF, 10 V, +/- 10%, X7R, 0603", Cap_Case=0603, Manufacturer=AVX, Supplier Part Number 1=478-7939-1-ND, TempCo=X7R, Tolerance_%=10%, Value1=Unknown, Value2=10V, ValueDisplayed=0.1uF
C10: library part CMP-0007498-4, "CAP, CERM, 4.7 uF, 10 V, +/- 20%, X7R, 0603", Cap_Case=0603, Manufacturer=MuRata, TempCo=X7R, Tolerance_%=20%, Value1=Unknown, Value2=10V, ValueDisplayed=4.7uF
C12: library part CMP-0006826-4, "CAP, CERM, 1000 pF, 16 V, +/- 10%, X7R, 0603", Cap_Case=0603, Manufacturer="Wurth Elektronik", Supplier Part Number 1=710-885012206034, TempCo=X7R, Tolerance_%=10%, Value1=Unknown, Value2=16V, ValueDisplayed=1000pF
C13: library part CMP-0007696-2, "CAP, CERM, 1 uF, 50 V, +/- 10%, X7R, 0805", Cap_Case=0805, Manufacturer="Wurth Elektronik", Supplier Part Number 1=710-885012207103, TempCo=X7R, Tolerance_%=10%, Value1=Unknown, Value2=50V, ValueDisplayed=1uF
C14: library part CMP-0009912-2, "CAP, AL, 330 uF, 63 V, +/- 20%, AEC-Q200 Grade 2, TH", Cap_Case=12.5x20mm, Manufacturer=Chemi-Con, Supplier Part Number 1=565-2043-ND, Tolerance_%=20%, Value1=Unknown, Value2=63V, ValueDisplayed=330uF
C15 C22: library part CMP-0008801-2, "CAP, CERM, 1 uF, 100 V, +/- 10%, X7R, 1206", Cap_Case=1206, Manufacturer=Samsung, Supplier Part Number 1=1276-1838-1-ND, TempCo=X7R, Tolerance_%=10%, Value1=Unknown, Value2=100V, ValueDisplayed=1uF
C16 C21: library part CMP-0007099-4, "CAP, CERM, 0.1 uF, 100 V, +/- 10%, X7S, AEC-Q200 Grade 1, 0603", Cap_Case=0603, Manufacturer=TDK, Supplier Part Number 1=445-6938-1-ND, TempCo=X7S, Tolerance_%=10%, Value1="0.04959 ohm", Value2=100V, ValueDisplayed=0.1uF
C17 C20: library part CMP-0007082-4, "CAP, CERM, 0.01 uF, 100 V, +/- 10%, X7R, AEC-Q200 Grade 1, 0603", Cap_Case=0603, Manufacturer=TDK, Supplier Part Number 1=445-5812-1-ND, TempCo=X7R, Tolerance_%=10%, Value1="0.235428 ohm", Value2=100V, ValueDisplayed=0.01uF
C18 C19: library part CMP-0007081-4, "CAP, CERM, 1000 pF, 100 V, +/- 10%, X7R, AEC-Q200 Grade 1, 0603", Cap_Case=0603, Manufacturer=TDK, Supplier Part Number 1=445-5806-1-ND, TempCo=X7R, Tolerance_%=10%, Value1="1.97137 ohm", Value2=100V, ValueDisplayed=1000pF
D1 D4: library part CMP-0002888-2, "LED, Green, SMD", Color=Green, Manufacturer=Lite-On, Value1=W, Value2=2V
D2 D3: library part CMP-0002829-3, "LED, Red, SMD", Color=red, Manufacturer=Lite-On, Value1=W, Value2=2V
D5: library part CMP-0028882-2, "Diode, Schottky, 40 V, 0.75 A, AEC-Q101, SOD-323", Manufacturer="Infineon Technologies", Value1=0.75A, Value2=0.74V
D6: library part CMP-0078131-2, "LED, Red, SMD", Color=Red, Manufacturer=Lite-On, Power_TotalModule=62.5mW, Value1=.0625W, Value2=2V
D7: library part CMP-0002840-2, "LED, Green, SMD", Color=green, Manufacturer=Lite-On, Value1=W, Value2=2V
D8: library part CMP-0076943-3, "Diode, Switching, 90 V, 0.1 A, SOD-523F", Manufacturer="Comchip Technology", Value1=0.1A, Value2=1V
FID1 FID2 FID3: library part CMP-0077181-1, "Fiducial mark.  There is nothing to buy or mount.", Manufacturer=N/A
H1 H2 H3 H4: library part CMP-0003617-1, "Machine Screw, Round, #4-40 x 1/4, Nylon, Philips panhead", Manufacturer="B&F Fastener Supply", Supplier Part Number 1=H542-ND
H5 H6 H7 H8: library part CMP-0003610-1, "Standoff, Hex, 0.5\"L #4-40 Nylon", Manufacturer=Keystone, PartNumber=1902C, Supplier Part Number 1=36-1902C-ND
J1: library part CMP-0075406-2, "Header, 100mil, 3x2, Gold, TH", Color=Black, Current_A=6.3A, Manufacturer=Samtec, PartNumber=TSW-103-07-G-D, Supplier Part Number 1=SAM1028-03-ND, Voltage_V=550V
J2: library part CMP-0055311-1, "Receptacle, USB 2.0, Micro B, 5 Position, R/A, SMT", Color=Black, Current_A=1.8A, Manufacturer=Molex, Supplier Part Number 1=WM11263CT-ND, Voltage_V=30V
J3 J5: library part CMP-0002334-1, "Header, 100mil, 3x1, Gold, TH", Manufacturer="Sullins Connector Solutions", PartNumber=PBC03SAAN, Supplier Part Number 1=S1011E-03-ND
J4: library part CMP-0075409-2, "Header, 100mil, 4x1, Gold, TH", Color=Black, Current_A=6.3A, Manufacturer=Samtec, Supplier Part Number 1=SAM1029-04-ND, Voltage_V=550V
J6: library part CMP-0075429-1, "Header, 100mil, 16x2, Gold, TH", Color=Black, Current_A=6.3A, Manufacturer=Samtec, Supplier Part Number 1=SAM1028-16-ND, Voltage_V=550V
J7 J8: library part CMP-0074911-1, "Terminal Block, 5.08 mm, 3x1, Brass, TH", Color=Blue, Current_A=15A, Manufacturer="On-Shore Technology", PartNumber=ED120/3DS, Supplier Part Number 1=ED1610-ND, Voltage_V=300V
L1: library part CMP-0064683-2, "Inductor, Shielded, Powdered Iron, 47 uH, 0.39 A, 2.3 ohm, AEC-Q200 Grade 1, SMD", Manufacturer="Wurth Elektronik", Supplier Part Number 1=732-6947-1-ND, Value1="2.3 ohm", Value2=0.39A, ValueDisplayed=47uH
L2: library part CMP-0064681-2, "Inductor, Shielded, Powdered Iron, 22 uH, 0.6 A, 1.04 ohm, AEC-Q200 Grade 1, SMD", Manufacturer="Wurth Elektronik", Supplier Part Number 1=732-6945-1-ND, Value1="1.04 ohm", Value2=0.6A, ValueDisplayed=22uH
L3: library part CMP-0084877-1, "Inductor, Ferrite Bead, Ferrite, 3 A, 120 ohm, AEC-Q200 Grade 1, SMD", Manufacturer=MuRata, Value1="120 ohm", Value2=3A
L4: library part CMP-0094173-1, "1 µH Shielded - Inductor 19 A 3.1mOhm Max Nonstandard", Digikey Part Number=283-HCM1A1104V2-1R0-RCT-ND, Manufacturer=Eaton, Mouser Part Number=504-HCM1A1104V21R0-R, Operating Temperature Range="-55°C to +155°C", Self Resonant Frequency=38MHz, Test Frequency=100kHz, Tolerance_%=20%
LBL1: library part CMP-0003625-1, Manufacturer=Brady, Supplier Part Number 1=97C5133
Logo1: library part CMP-0074844-1
Logo2: library part CMP-0074838-1, "Texas Instrument Corporate Signature"
Logo3: library part CMP-0074847-1, "FCC_disclaimer"
Logo4: library part CMP-0074769-1
LOGO5 LOGO6: library part CMP-0074837-1, "IEC 61010-1 Hot Surface Warning"
NT1 NT2: library part CMP-0078142-4, "Single point connection between nets.", Manufacturer=N/A
Q1: library part CMP-0000467-2, "Transistor, NPN, 80 V, 1.5 A, AEC-Q101, SOT-23", Manufacturer="Diodes Inc.", Supplier Part Number 1=FMMT620CT-ND, Value1="1.5 A", Value2=900
Q2: library part CMP-0088880-1, "N-Channel 40V 8A (Ta) 15W (Tc) Surface Mount DFN2020MD-6", Digikey Part Number=1727-7413-1-ND, Drain To Source Breakdown Voltage=40V, Input Capacitace At Vds="637pF @ 20V", Manufacturer=Nexperia, Mouser Part Number=771-BUK9D23-40EX, Operating Temperature Range="-55°C to +175°C", Power_W=2.3W, Pulse Drain Current=76A, Typ Forward Diode Voltage=0.8V
R1 R2 R3 R6 R7 R8: library part CMP-0092019-1, "Res Thin Film 0603 10K Ohm 0.1% 1/10W ±10ppm/°C Molded SMD SMD Punched Carrier T/R", Digikey Part Number=P10KBDCT-ND, Manufacturer=Panasonic, Mouser Part Number=667-ERA-3ARB103V, Operating Temperature Range="-55°C to +155°C", Power_W=100mW, TempCo=10ppm/°C, Tolerance_%=0.1%
R4: library part CMP-0001776-2, "Trimmer Potentiometer, 25kohm, 0.5W, TH", Manufacturer=Bourns, Supplier Part Number 1=3352T-253LF-ND
R5 R12 R13: library part CMP-0025874-4, "RES, 0, 5%, 0.1 W, AEC-Q200 Grade 0, 0603", Manufacturer=Panasonic, Power_W=100mW, Supplier Part Number 1=P0.0GCT-ND, TempCo="600 ppm/C", Tolerance_%=5%, Value2=0.1W, Value_Code=0000, ValueDisplayed=0
R9 R10 R11: library part CMP-0025830-4, "RES, 5.1 k, 5%, 0.1 W, AEC-Q200 Grade 0, 0603", Manufacturer=Vishay-Dale, Power_W=100mW, Supplier Part Number 1=541-5.1KGCT-ND, TempCo="200 ppm/C", Tolerance_%=5%, Value2=0.1W, Value_Code=5k10, ValueDisplayed=5.1k
R14: library part CMP-0015919-3, "RES, 22, 5%, 1.5 W, AEC-Q200 Grade 0, 2512", Manufacturer=Vishay-Dale, Power_W=1.5W, TempCo="200 ppm/C", Tolerance_%=5%, Value_Code=22R0, ValueDisplayed=22
R15 R16: library part CMP-0022895-5, "RES, 1.00 k, 1%, 0.1 W, 0603", Manufacturer=Yageo, Power_W=100mW, Supplier Part Number 1=311-1.00KHRCT-ND, TempCo="100 ppm/C", Tolerance_%=1%, Value2=0.1W, Value_Code=1k00, ValueDisplayed=1.00k
R17 R20 R21: library part CMP-0025924-5, "RES, 470, 5%, 0.1 W, 0603", Manufacturer=Yageo, Power_W=100mW, Supplier Part Number 1=311-470GRCT-ND, TempCo="100 ppm/C", Tolerance_%=5%, Value2=0.1W, Value_Code=470R, ValueDisplayed=470
R18: library part CMP-0024300-2, "RES, 4.70 k, 0.1%, 0.1 W, 0603", Manufacturer="Yageo America", Power_W=100mW, TempCo="25 ppm/C", Tolerance_%=0.1%, Value2=0.1W, Value_Code=4k70, ValueDisplayed=4.70k
R19: library part CMP-0025925-5, "RES, 47 k, 5%, 0.1 W, 0603", Manufacturer=Yageo, Power_W=100mW, Supplier Part Number 1=311-47KGRCT-ND, TempCo="100 ppm/C", Tolerance_%=5%, Value2=0.1W, Value_Code=47k0, ValueDisplayed=47k
R22 R23: library part CMP-0025701-4, "RES, 10 k, 5%, 0.1 W, AEC-Q200 Grade 0, 0603", Manufacturer=Vishay-Dale, Power_W=100mW, Supplier Part Number 1=541-10KGCT-ND, TempCo="200 ppm/C", Tolerance_%=5%, Value2=0.1W, Value_Code=10k0, ValueDisplayed=10k
R24: library part CMP-0018760-2, "RES, 0, 5%, 0.25 W, AEC-Q200 Grade 0, 1206", Manufacturer=Vishay-Dale, Power_W=250mW, Supplier Part Number 1=541-2239-1-ND, TempCo=ppm/C, Tolerance_%=5%, Value2=0.25W, Value_Code=0000, ValueDisplayed=0
S1 S2 S3: library part CMP-0002155-2, "SWITCH TOGGLE SPDT 0.4VA 28V", CurrentRating_mA=100A, Manufacturer="NKK Switches", PartNumber=B12AP, Supplier Part Number 1=360-1012-ND
S4: library part CMP-0002196-2, "Switch, Tactile, SPST, 12 V, SMD", CurrentRating_mA=50A, Manufacturer="Wurth Elektronik", PartNumber=434121025816, Supplier Part Number 1=31T8978
SH-J1 SH-J2 SH-J3 SH-J4 SH-J5 SH-J6 SH-J7 SH-J8 SH-J9 SH-J10 SH-J11 SH-J12 SH-J13 SH-J14 SH-J15 SH-J16 SH-J17 SH-J18 SH-J19: library part CMP-0003623-3, "Shunt, 100mil, Gold plated, Black", Alternate Manufacturer=3M, Alternate PartNumber=969102-0000-DA, Manufacturer=Samtec, Supplier Part Number 1=SAM8858-ND
TP1 TP2 TP3 TP4 TP10 TP11 TP12 TP13: library part CMP-0055139-1, "Test Point, Miniature, White, TH", Color=White, Manufacturer=Keystone, PartNumber=5002, Supplier Part Number 1=36-5002-ND
TP5 TP6 TP7 TP8 TP9 TP14 TP15 TP16 TP17 TP18 TP19 TP20: library part CMP-0055137-1, "Test Point, Miniature, Red, TH", Color=Red, Manufacturer=Keystone, PartNumber=5000, Supplier Part Number 1=36-5000-ND
TP21 TP22: library part CMP-0055142-1, "Test Point, Compact, Red, TH", Color=Red, Manufacturer=Keystone, PartNumber=5005, Supplier Part Number 1=36-5005-ND
TP23 TP28 TP29 TP30 TP31: library part CMP-0055138-1, "Test Point, Miniature, Black, TH", Color=Black, Manufacturer=Keystone, PartNumber=5001, Supplier Part Number 1=36-5001-ND
TP24 TP25 TP26 TP27: library part CMP-0075110-1, "1mm Uninsulated Shorting Plug, 10.16mm spacing, TH", Manufacturer=Harwin, PartNumber=D3082-05, Supplier Part Number 1=952-1873-ND
U1: library part CMP-0001322-1, "Sensorless Field Oriented Control (FOC) Integrated FET BLDC Driver, WQFN32", Manufacturer="Texas Instruments", Max Supply Voltage=35V, Min Supply Voltage=4.5V, Nominal Supply Current=11-28mA, Operating Temperature Range="-40°C to +150°C"
U2: library part CMP-0121693-1, "UART Interface IC USB Full Speed to Serial UART IC, Includes Oscillator and EEPROM, SSOP-28", Digikey Part Number=768-FT232RNL-REELCT-ND, Manufacturer=FTDI, Max Supply Voltage=5.25V, Min Supply Voltage=1.8V, Mouser Part Number=895-FT232RNL-REEL, Nominal Supply Current=7mA, Operating Temperature Range="-40°C to +85°C"
U3: library part CMP-0043115-3, "4-Channel ESD Protection Array for High-Speed Data Interfaces, DRY0006A (USON-6)", Breakdown Voltage(Min)(V)=6, IO Capacitance(Typ)(pF)=1.6, IO Leakage Current(nA)=1, Manufacturer="Texas Instruments", Operating Temperature Range="-40 to 85 C", Rating=Catalog
U4: library part CMP-0089204-1, "CPU16 MSP430™ FRAM Microcontroller IC 16-Bit 24MHz 32KB (32K x 8) FRAM 48-LQFP (7x7)", Digikey Part Number=296-50261-1-ND, Frequency_Fixed=24MHz, Manufacturer="Texas Instruments", Max Supply Voltage=3.6V, Min Supply Voltage=1.8V, Mouser Part Number=595-MSP430FR2355TPTR, Operating Temperature Range="-40°C to +105°C"
Y1: library part CMP-0084387-1, "Resonator, 4 MHz, 39 pF, AEC-Q200 Grade 1, SMD", Frequency_Fixed=4MHz, Load Capacitance="39 pF", Manufacturer=MuRata
ZZ1: library part CMP-0003616-3
ZZ2: library part CMP-0077236-1
ZZ3: library part CMP-0077237-1
ZZ4: library part CMP-0077238-1

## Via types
v1: diameter 20, hole 10, Top Layer to Bottom Layer, tented both sides, 580 vias
v2: diameter 30, hole 10, Top Layer to Bottom Layer, tented both sides, 42 vias
v3: diameter 19.68, hole 7.87, Top Layer to Bottom Layer, tented both sides, 11 vias

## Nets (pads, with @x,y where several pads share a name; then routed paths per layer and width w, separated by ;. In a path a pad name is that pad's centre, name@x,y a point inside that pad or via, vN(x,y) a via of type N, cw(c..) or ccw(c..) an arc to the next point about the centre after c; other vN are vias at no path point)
3V3_MCU: C13.1 D5.1 J4.2 J5.2 R19.2 R20.2 R21.2 TP20.1 U4.6 | length 434.2
  Top Layer w10: R19.2@260.06,1637.5 v1(297.5,1637.5) ; 627.54,1275.51 640.11,1262.93 693.3,1262.93 v1(752.5,1262.93) ; v1(1131.95,1214.99) 1148.39,1231.43 R21.2@1182.08,1231.43 ; v1(1137.5,1370) 1181.88,1370 R20.2@1182.08,1370.2
  Top Layer w20: C13.1@572.03,1287.5 615.54,1287.5 627.54,1275.51 ; TP20.1@1175,525 1185.81,514.19 D5.1@1185.81,425
3V3COM: C9.1 D5.2 J5.3 TP16.1 U2.4 U2.17 | length 1382.9
  Top Layer w15: U2.17@581.82,569.59 581.82,635.04 644.88,698.09 746.19,698.09 786.55,738.45 786.55,841.24 786.55,894.06 C9.1@819.58,927.09
  Top Layer w20: 786.55,738.45 TP16.1@1000,525 J5.3@1400,125
3V3EXT: J5.1 TP19.1 | length 485.1
  Top Layer w20: TP19.1@1175,125 1247.5,52.5 1527.5,52.5 J5.1@1600,125
5V_EXT: J3.1 TP18.1 | length 212.5
  Top Layer w20: J3.1@787.5,125 TP18.1@1000,125
5V_USB: C8.1 J3.3 L3.1 TP17.1 U3.6 | length 510.5
  Top Layer w10: v1(407.5,542.5) 414.91,549.91 U3.6@428.19,549.91
  Top Layer w30: 355.49,515.64 587.5,283.63 J3.3@587.5,125
  other v1: 349.64,538.74 349.78,565.08 349.64,594.33
5VCC: C10.2 C11.1 J3.2 U2.20 | length 438.4
  Top Layer w10: U2.20@658.32,567.89 658.6,461.54
  Top Layer w25: J3.2@687.5,125 687.73,125.23 C11.1@687.73,456.96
